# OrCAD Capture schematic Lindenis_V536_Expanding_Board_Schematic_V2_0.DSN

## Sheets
1 13 CON: size A3; title: Lindenis V536; rev: 1.1; note: CON
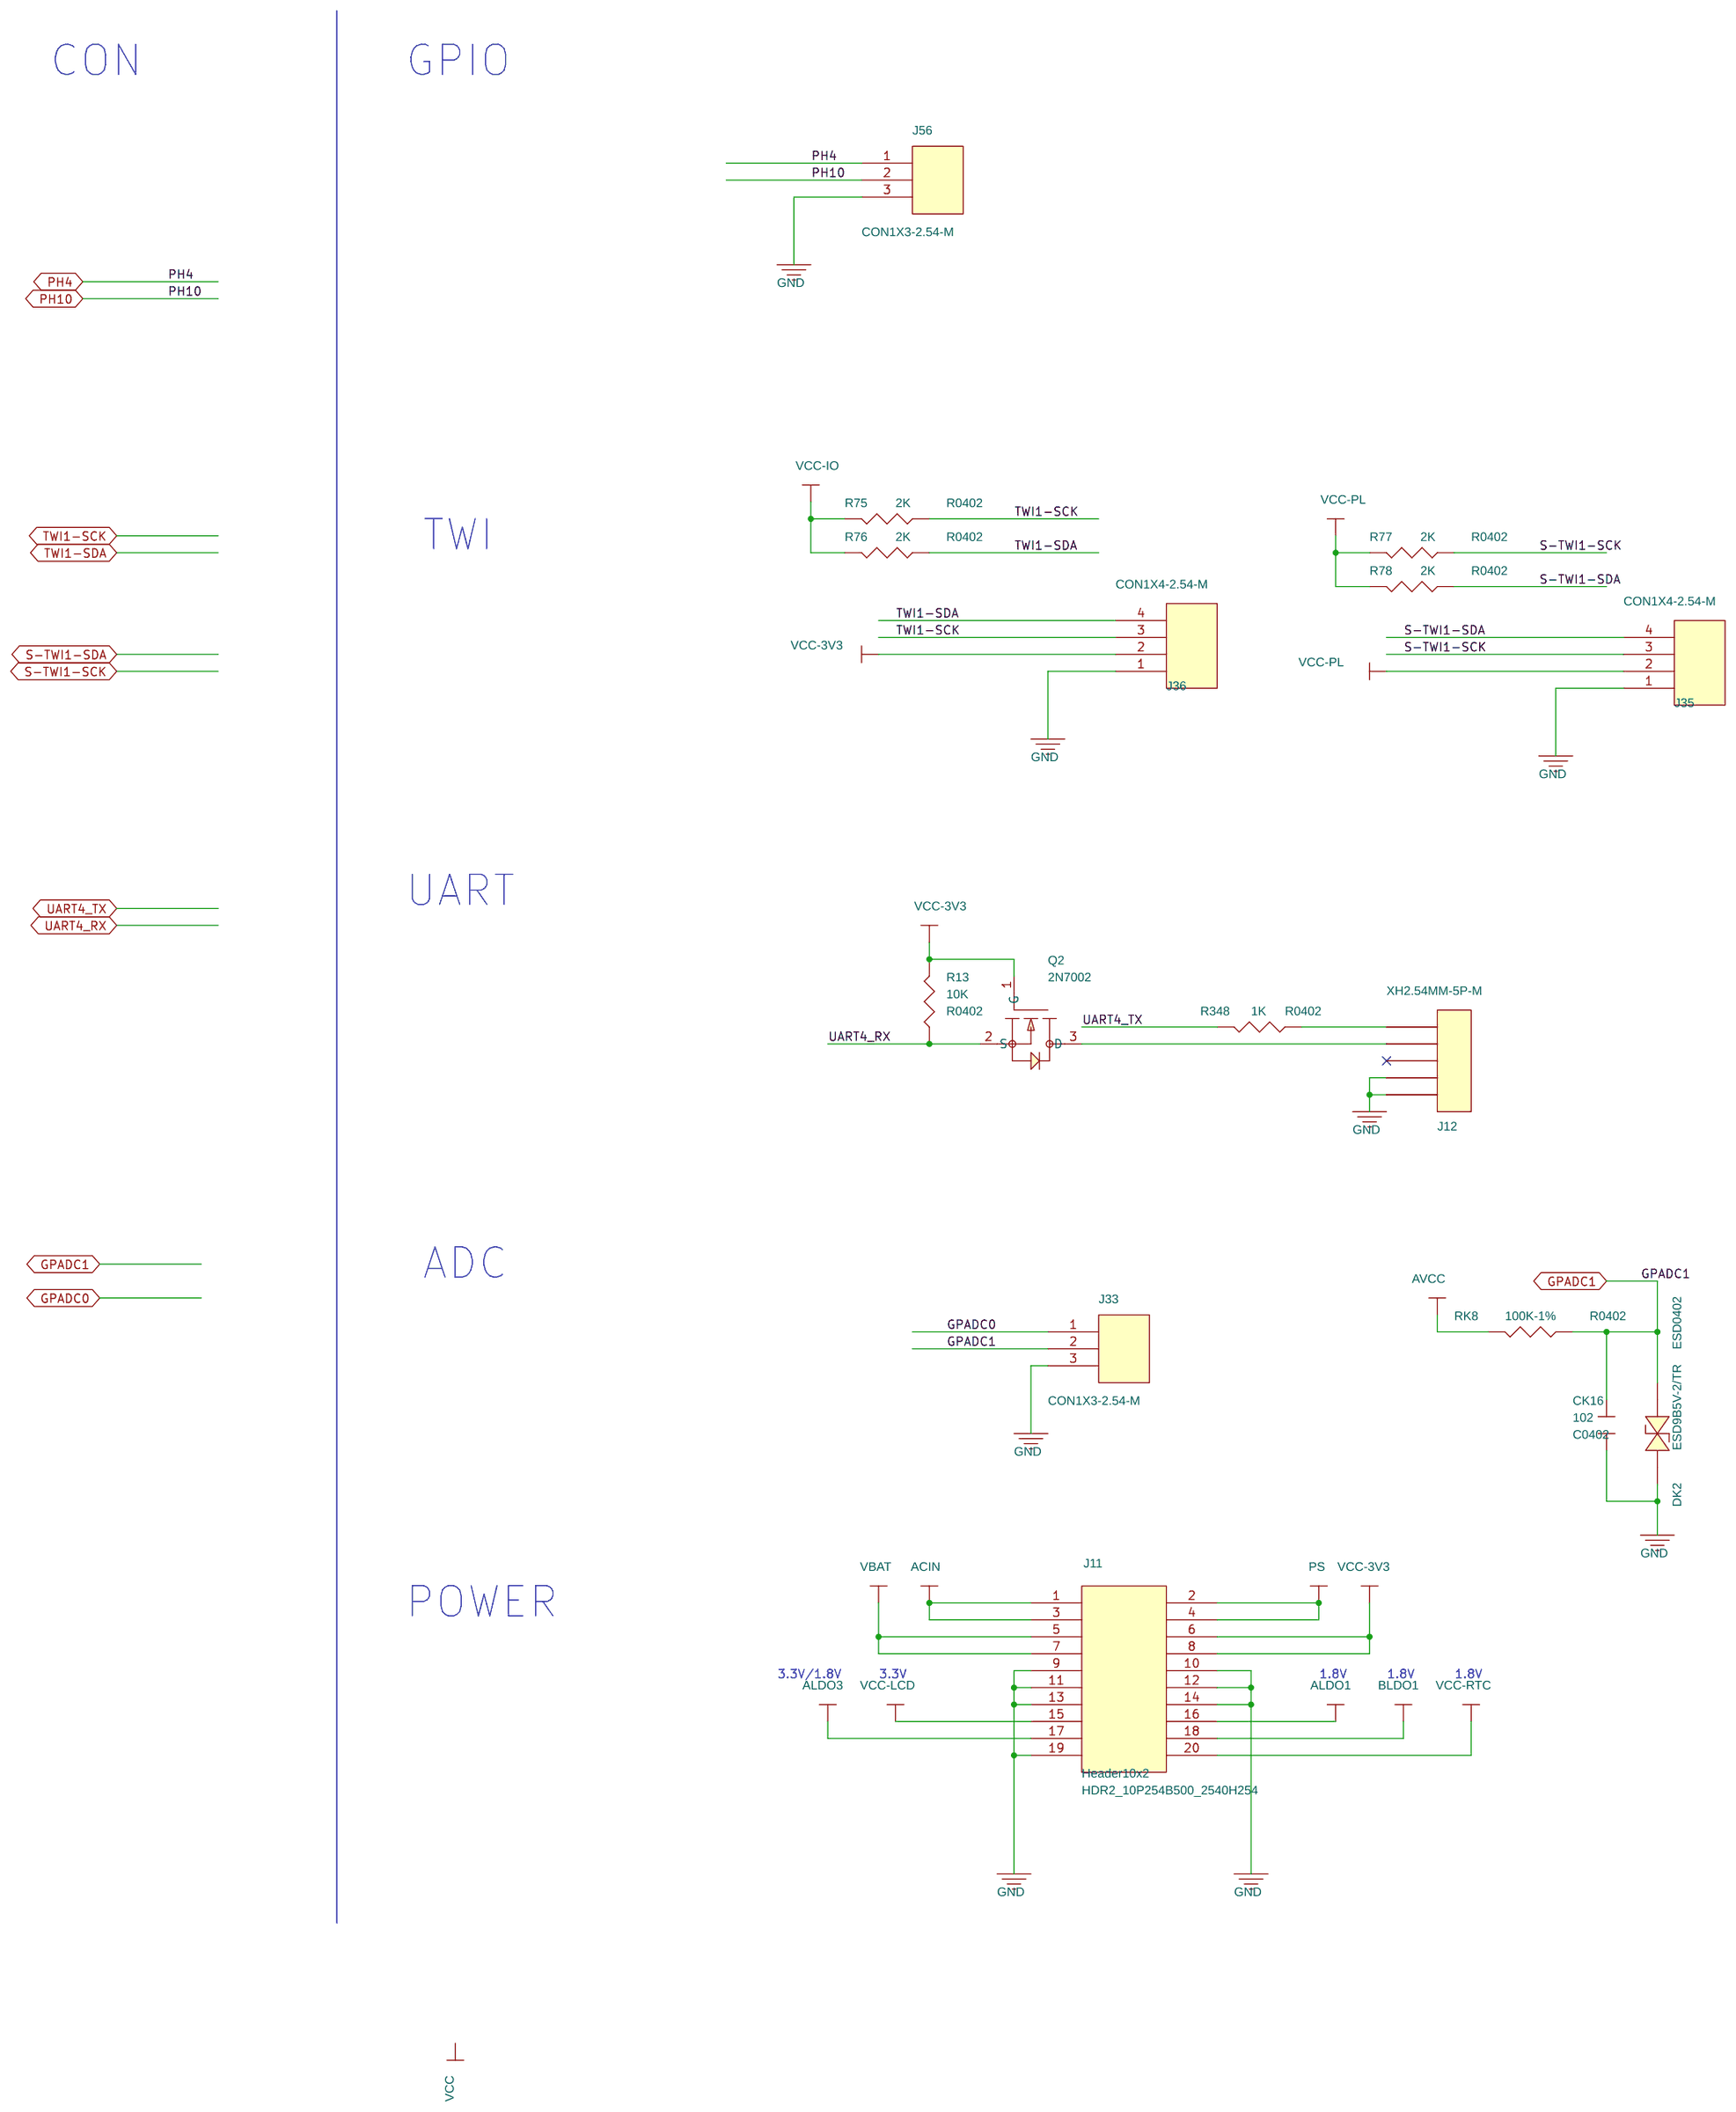
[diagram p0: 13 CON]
2 06 HDMI: size A3; note: HDMI
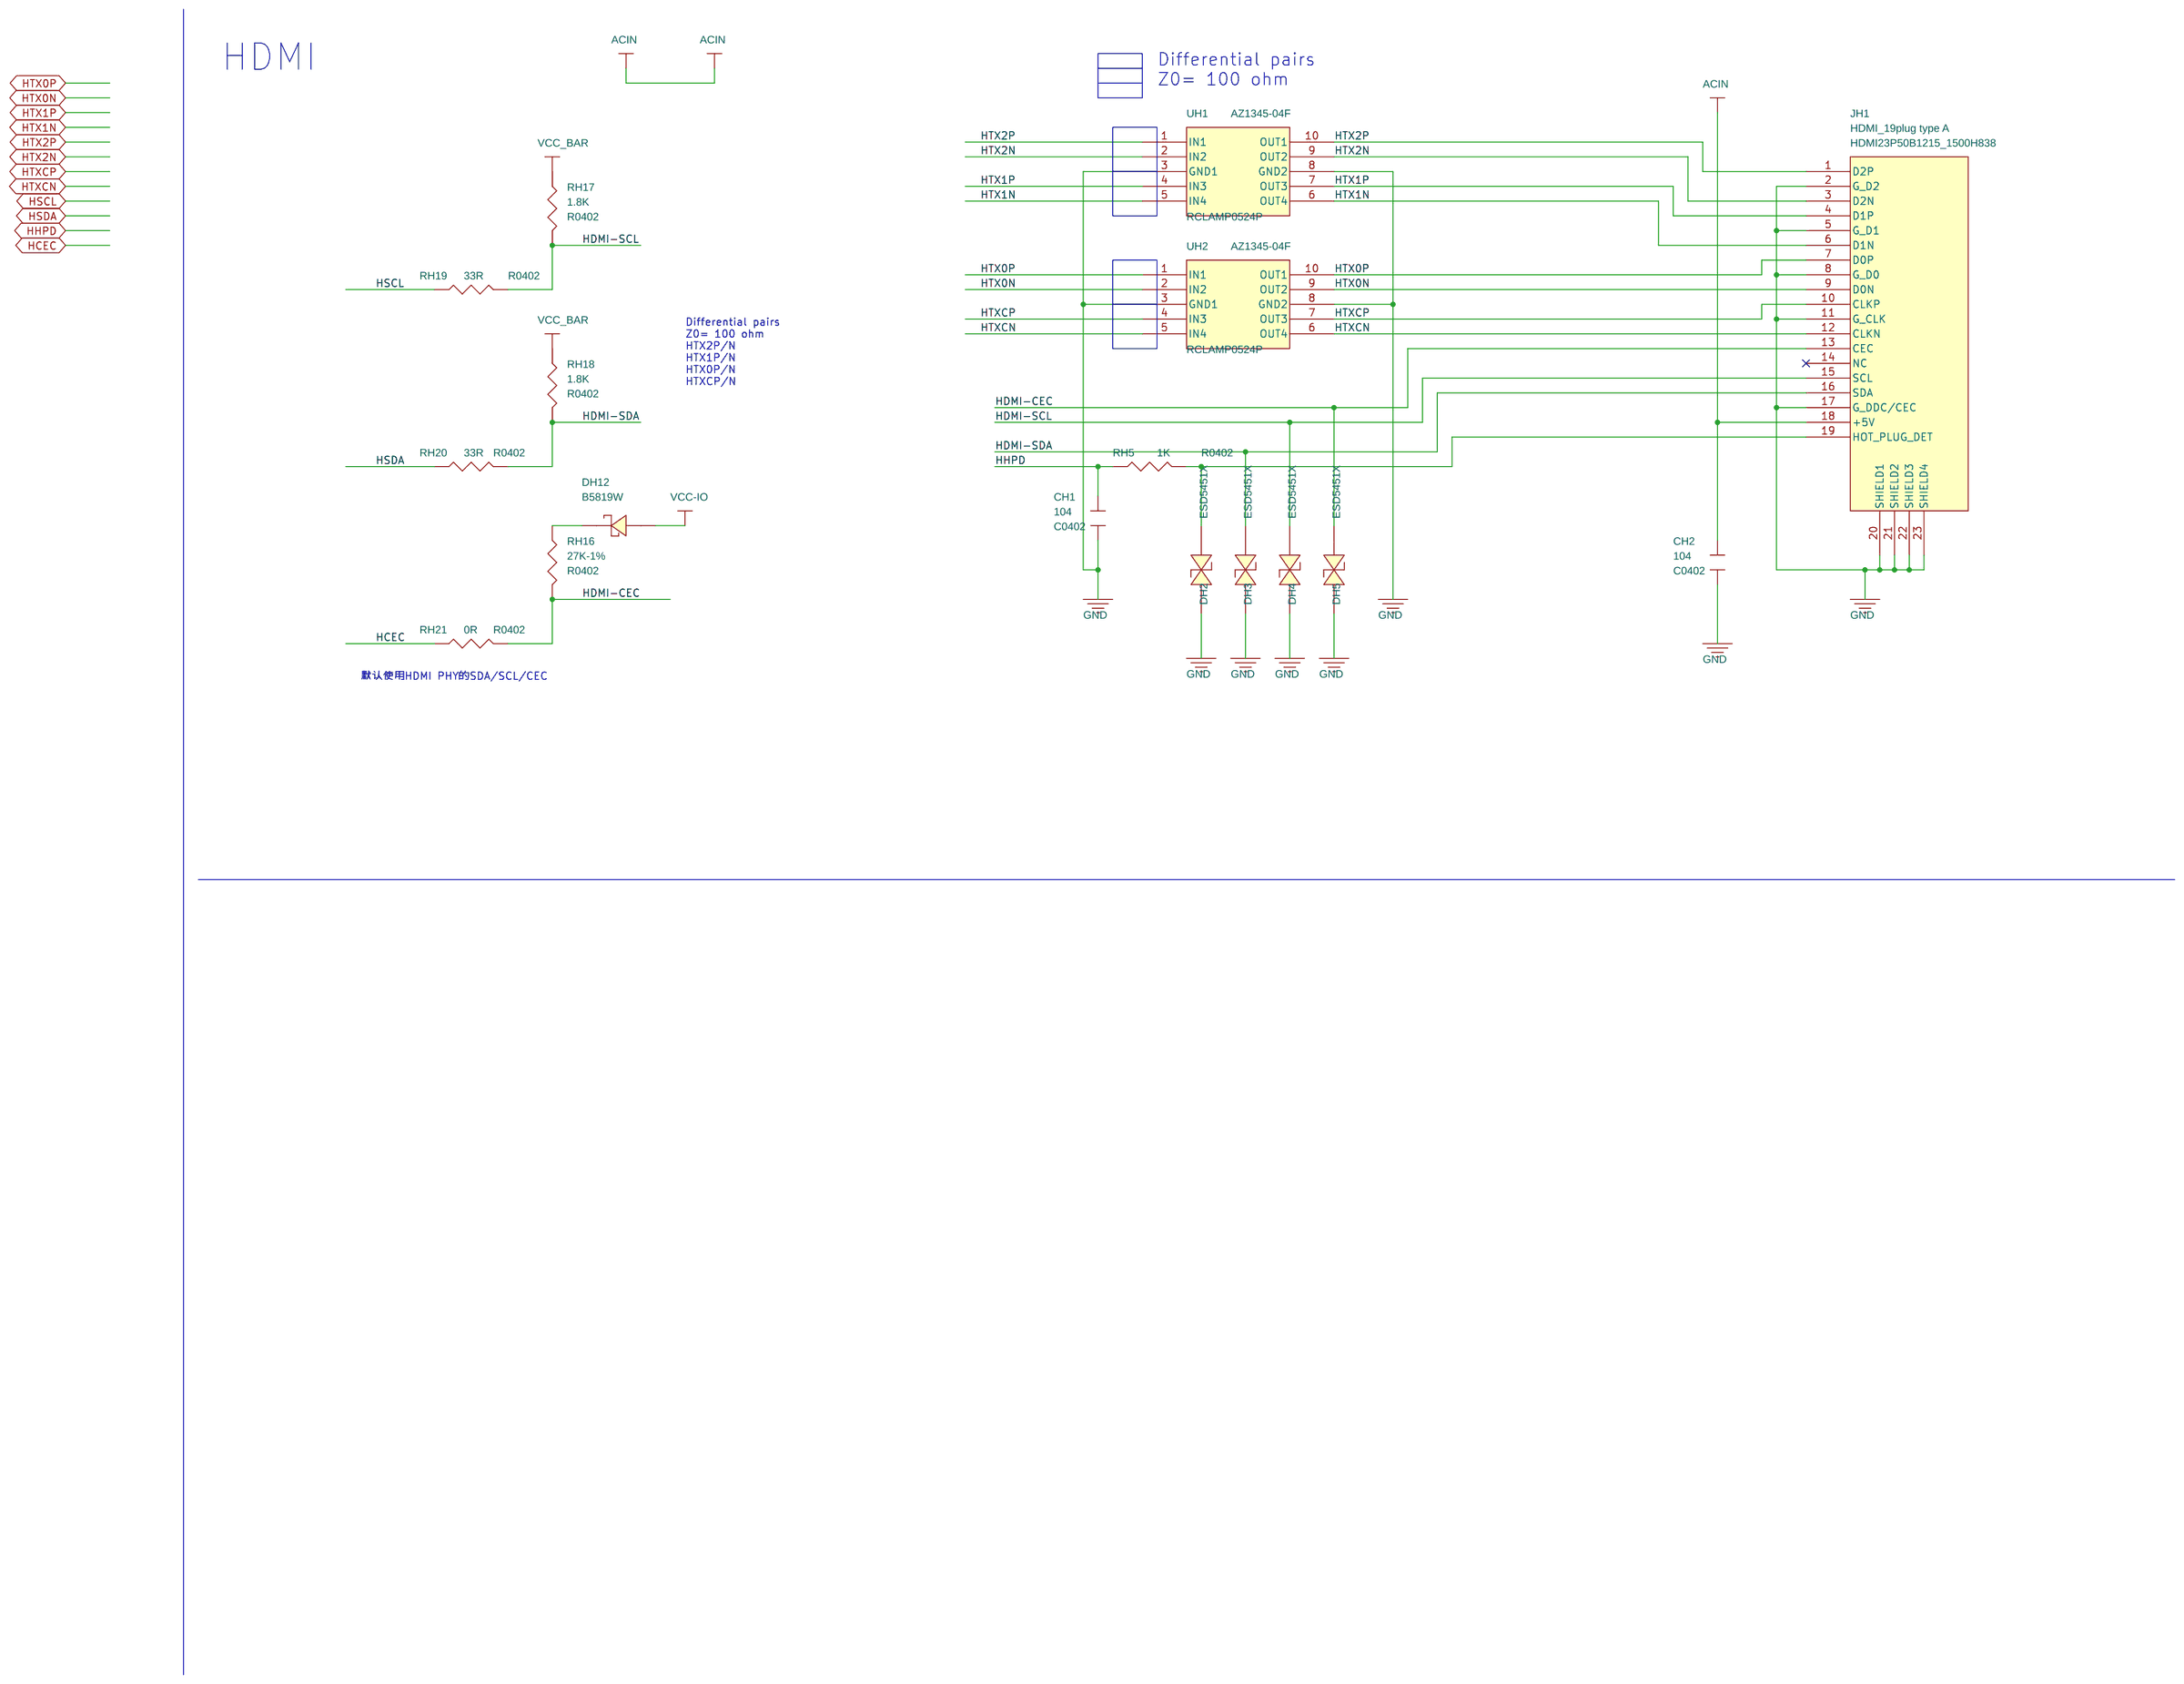
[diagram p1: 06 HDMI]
3 12 GMAC: size A3; note: ETHERNET
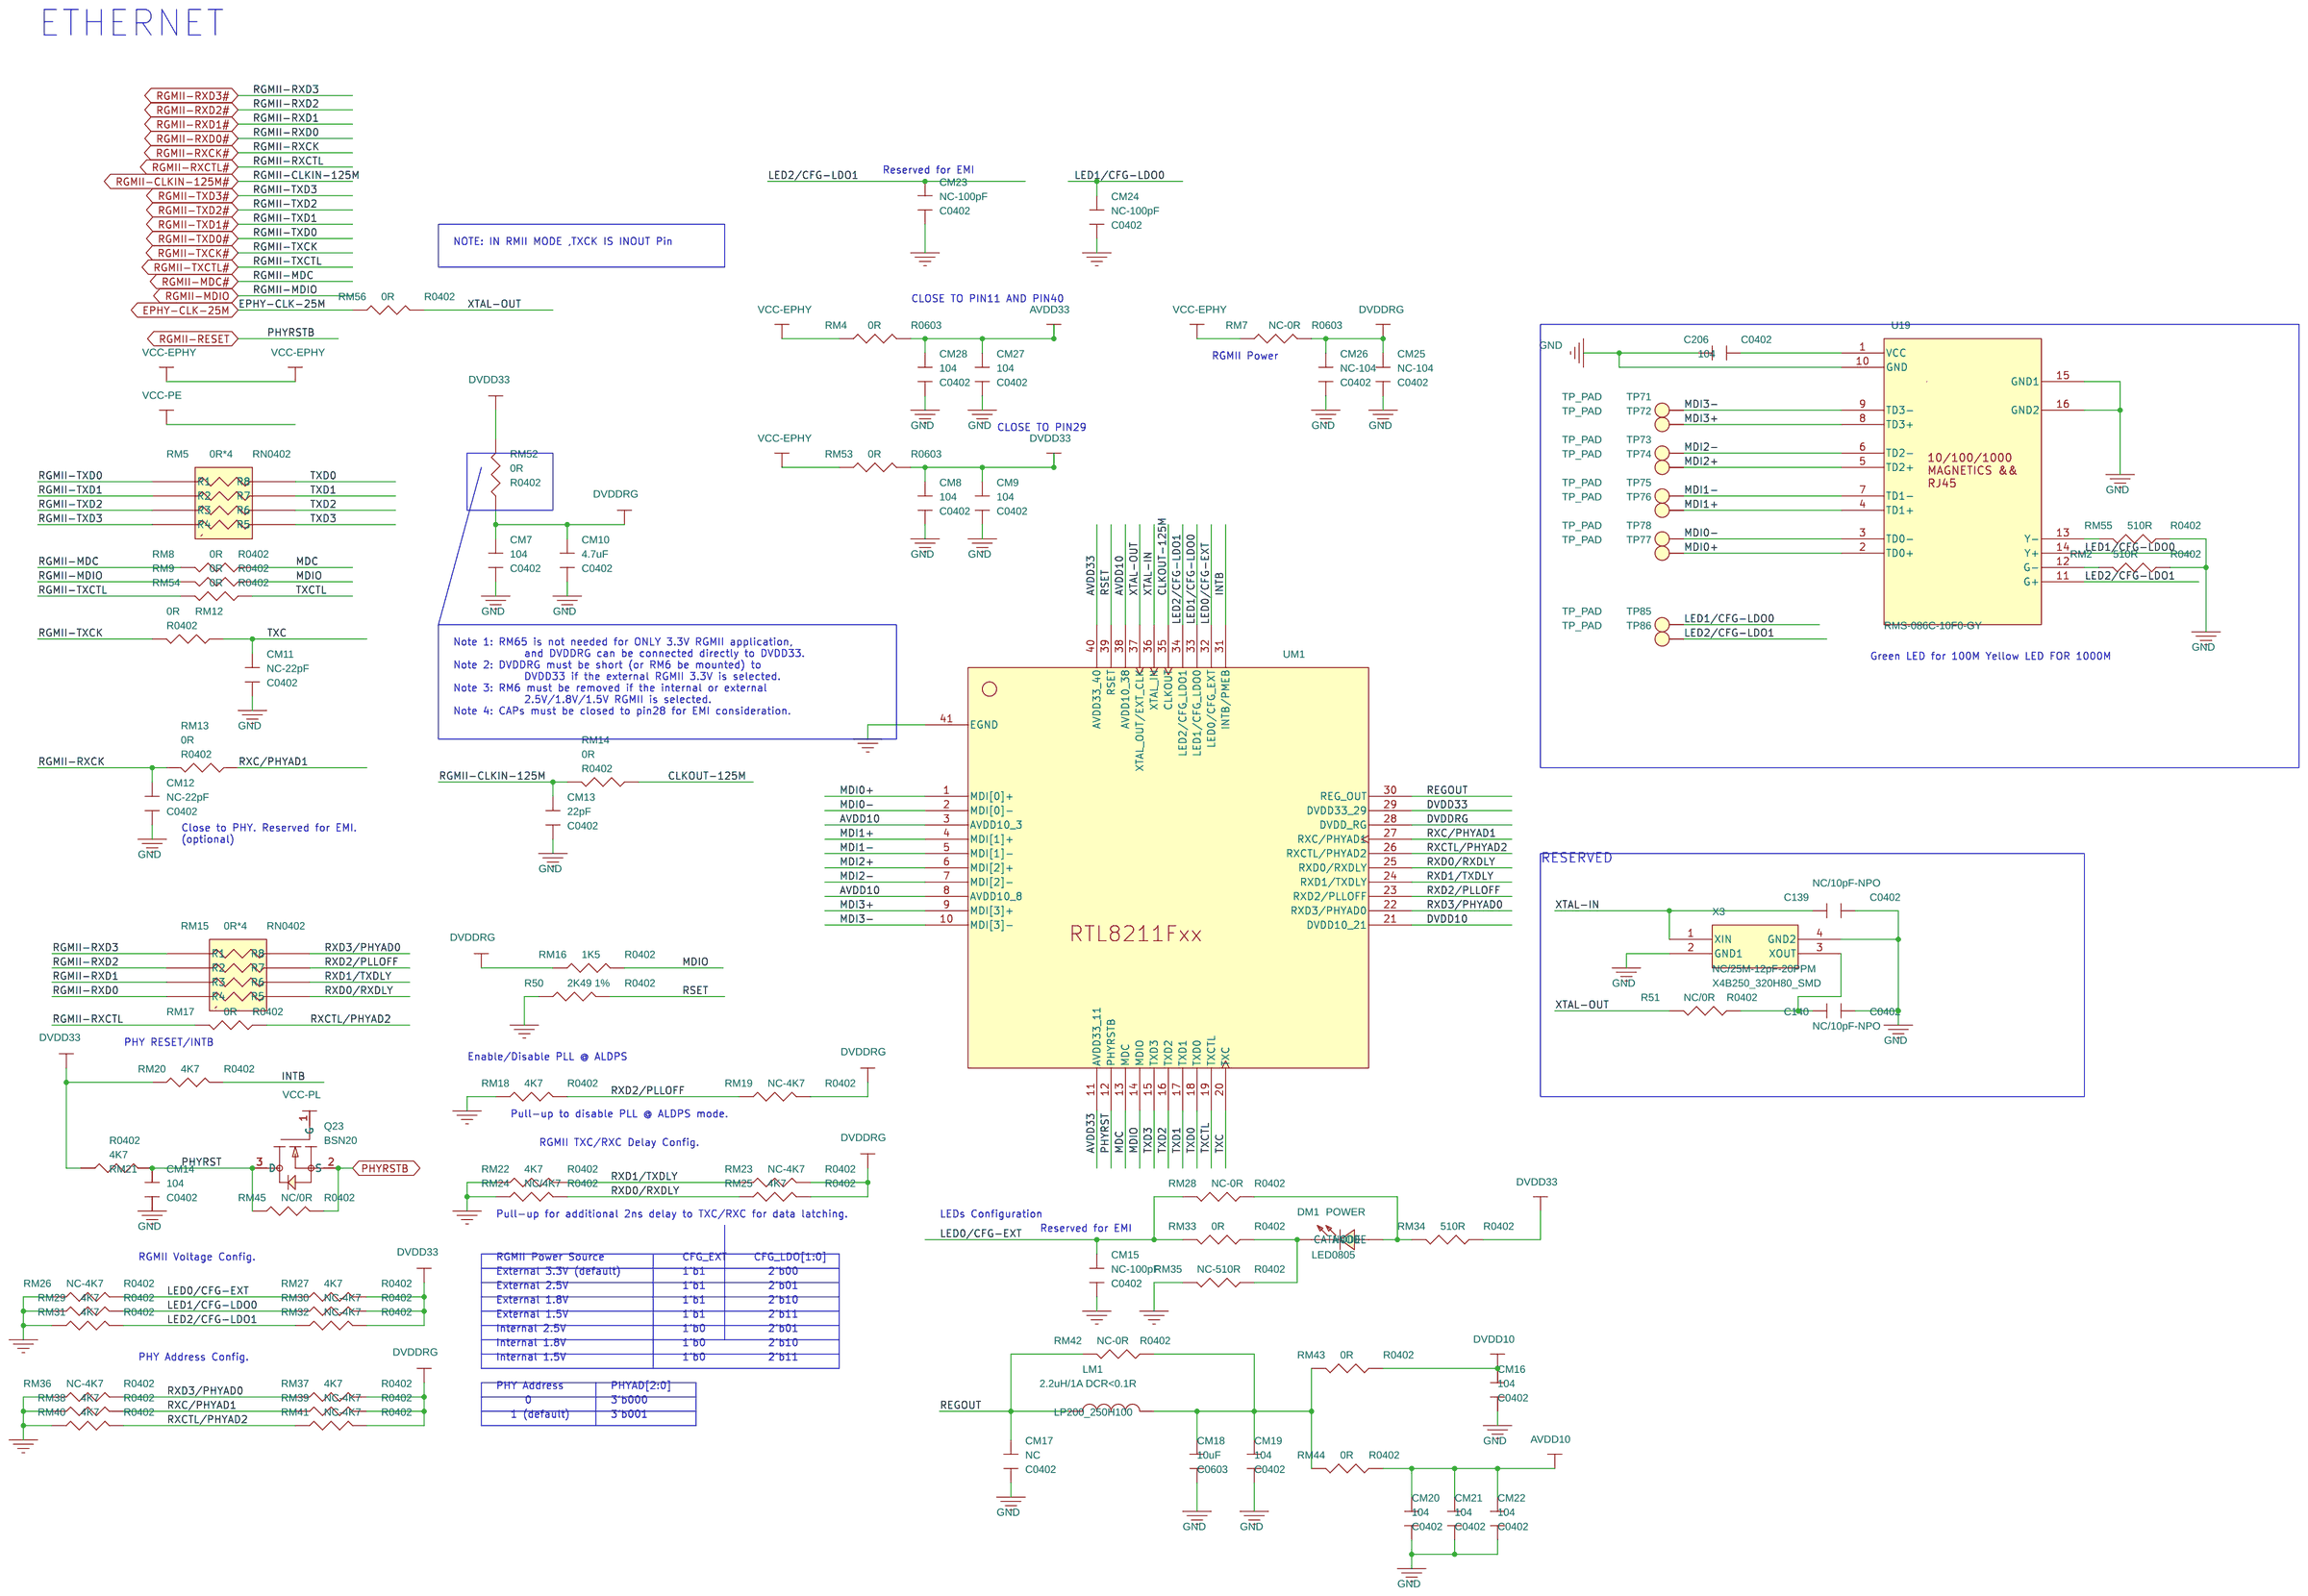
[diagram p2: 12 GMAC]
4 11 4G-SIM7600CE: size A3; title: Lindenis Airdoc V5; note: SIM7600CE
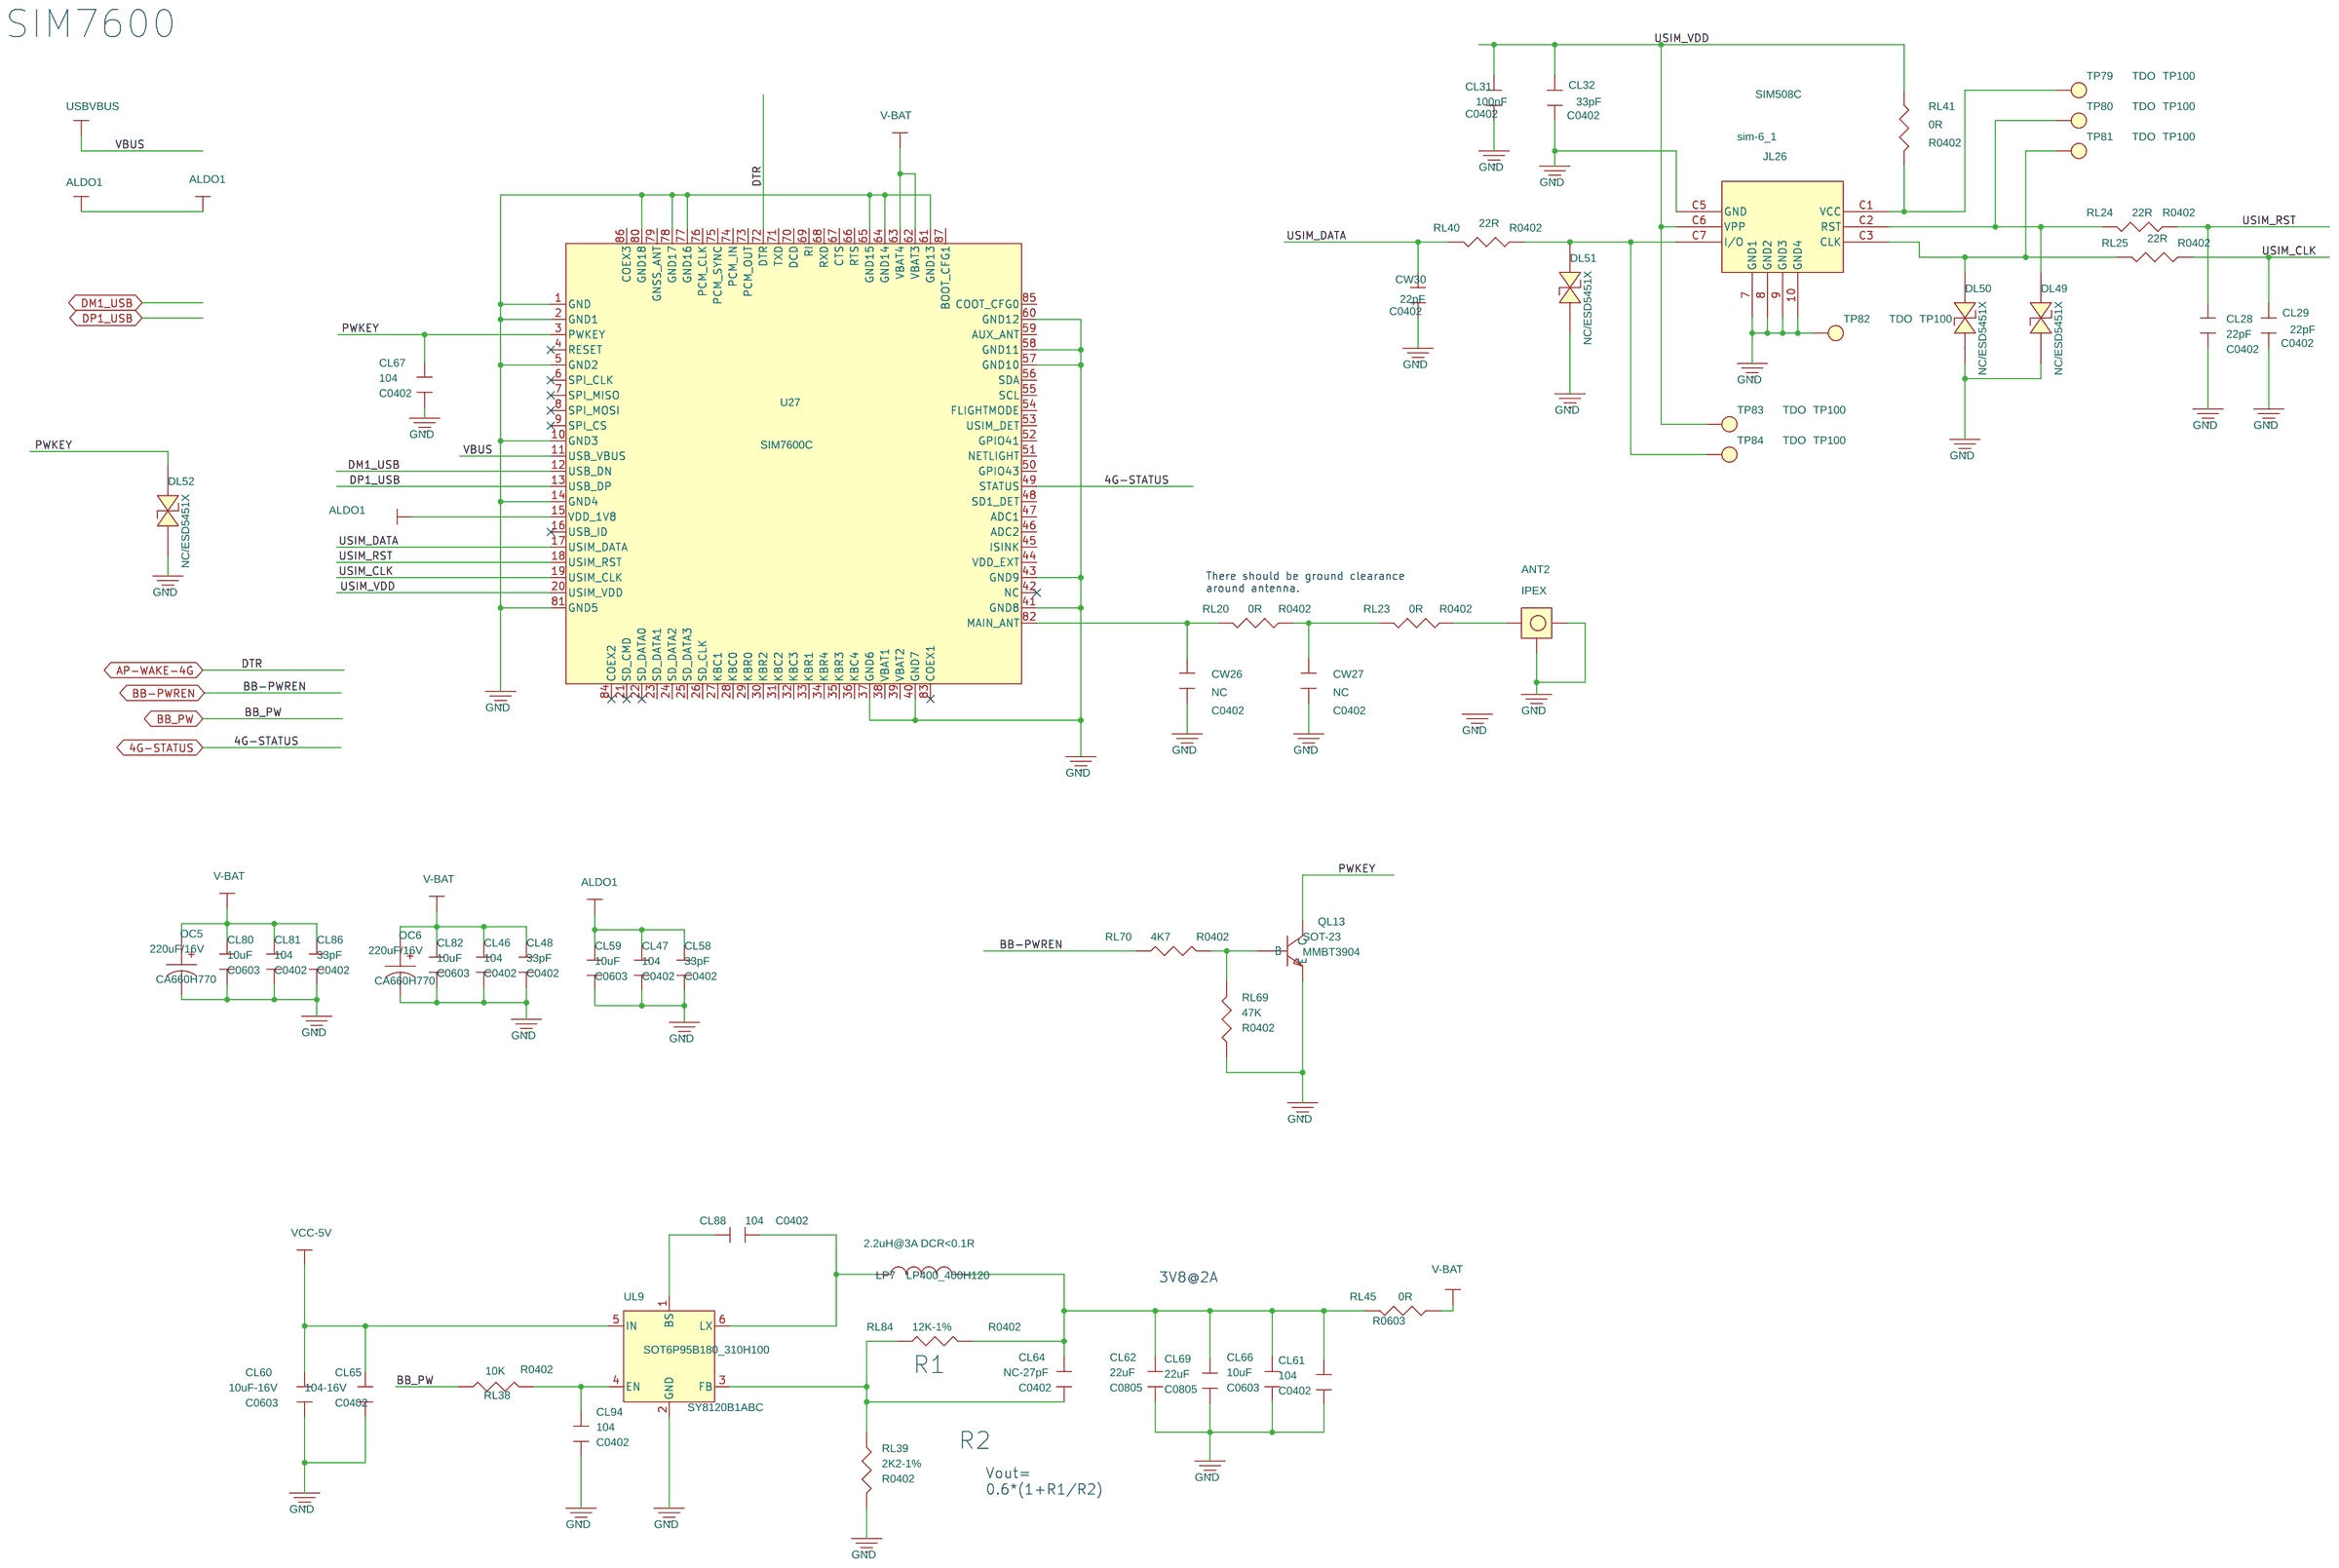
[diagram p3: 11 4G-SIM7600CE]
5 02 V536MODE: size A3; note: MODE
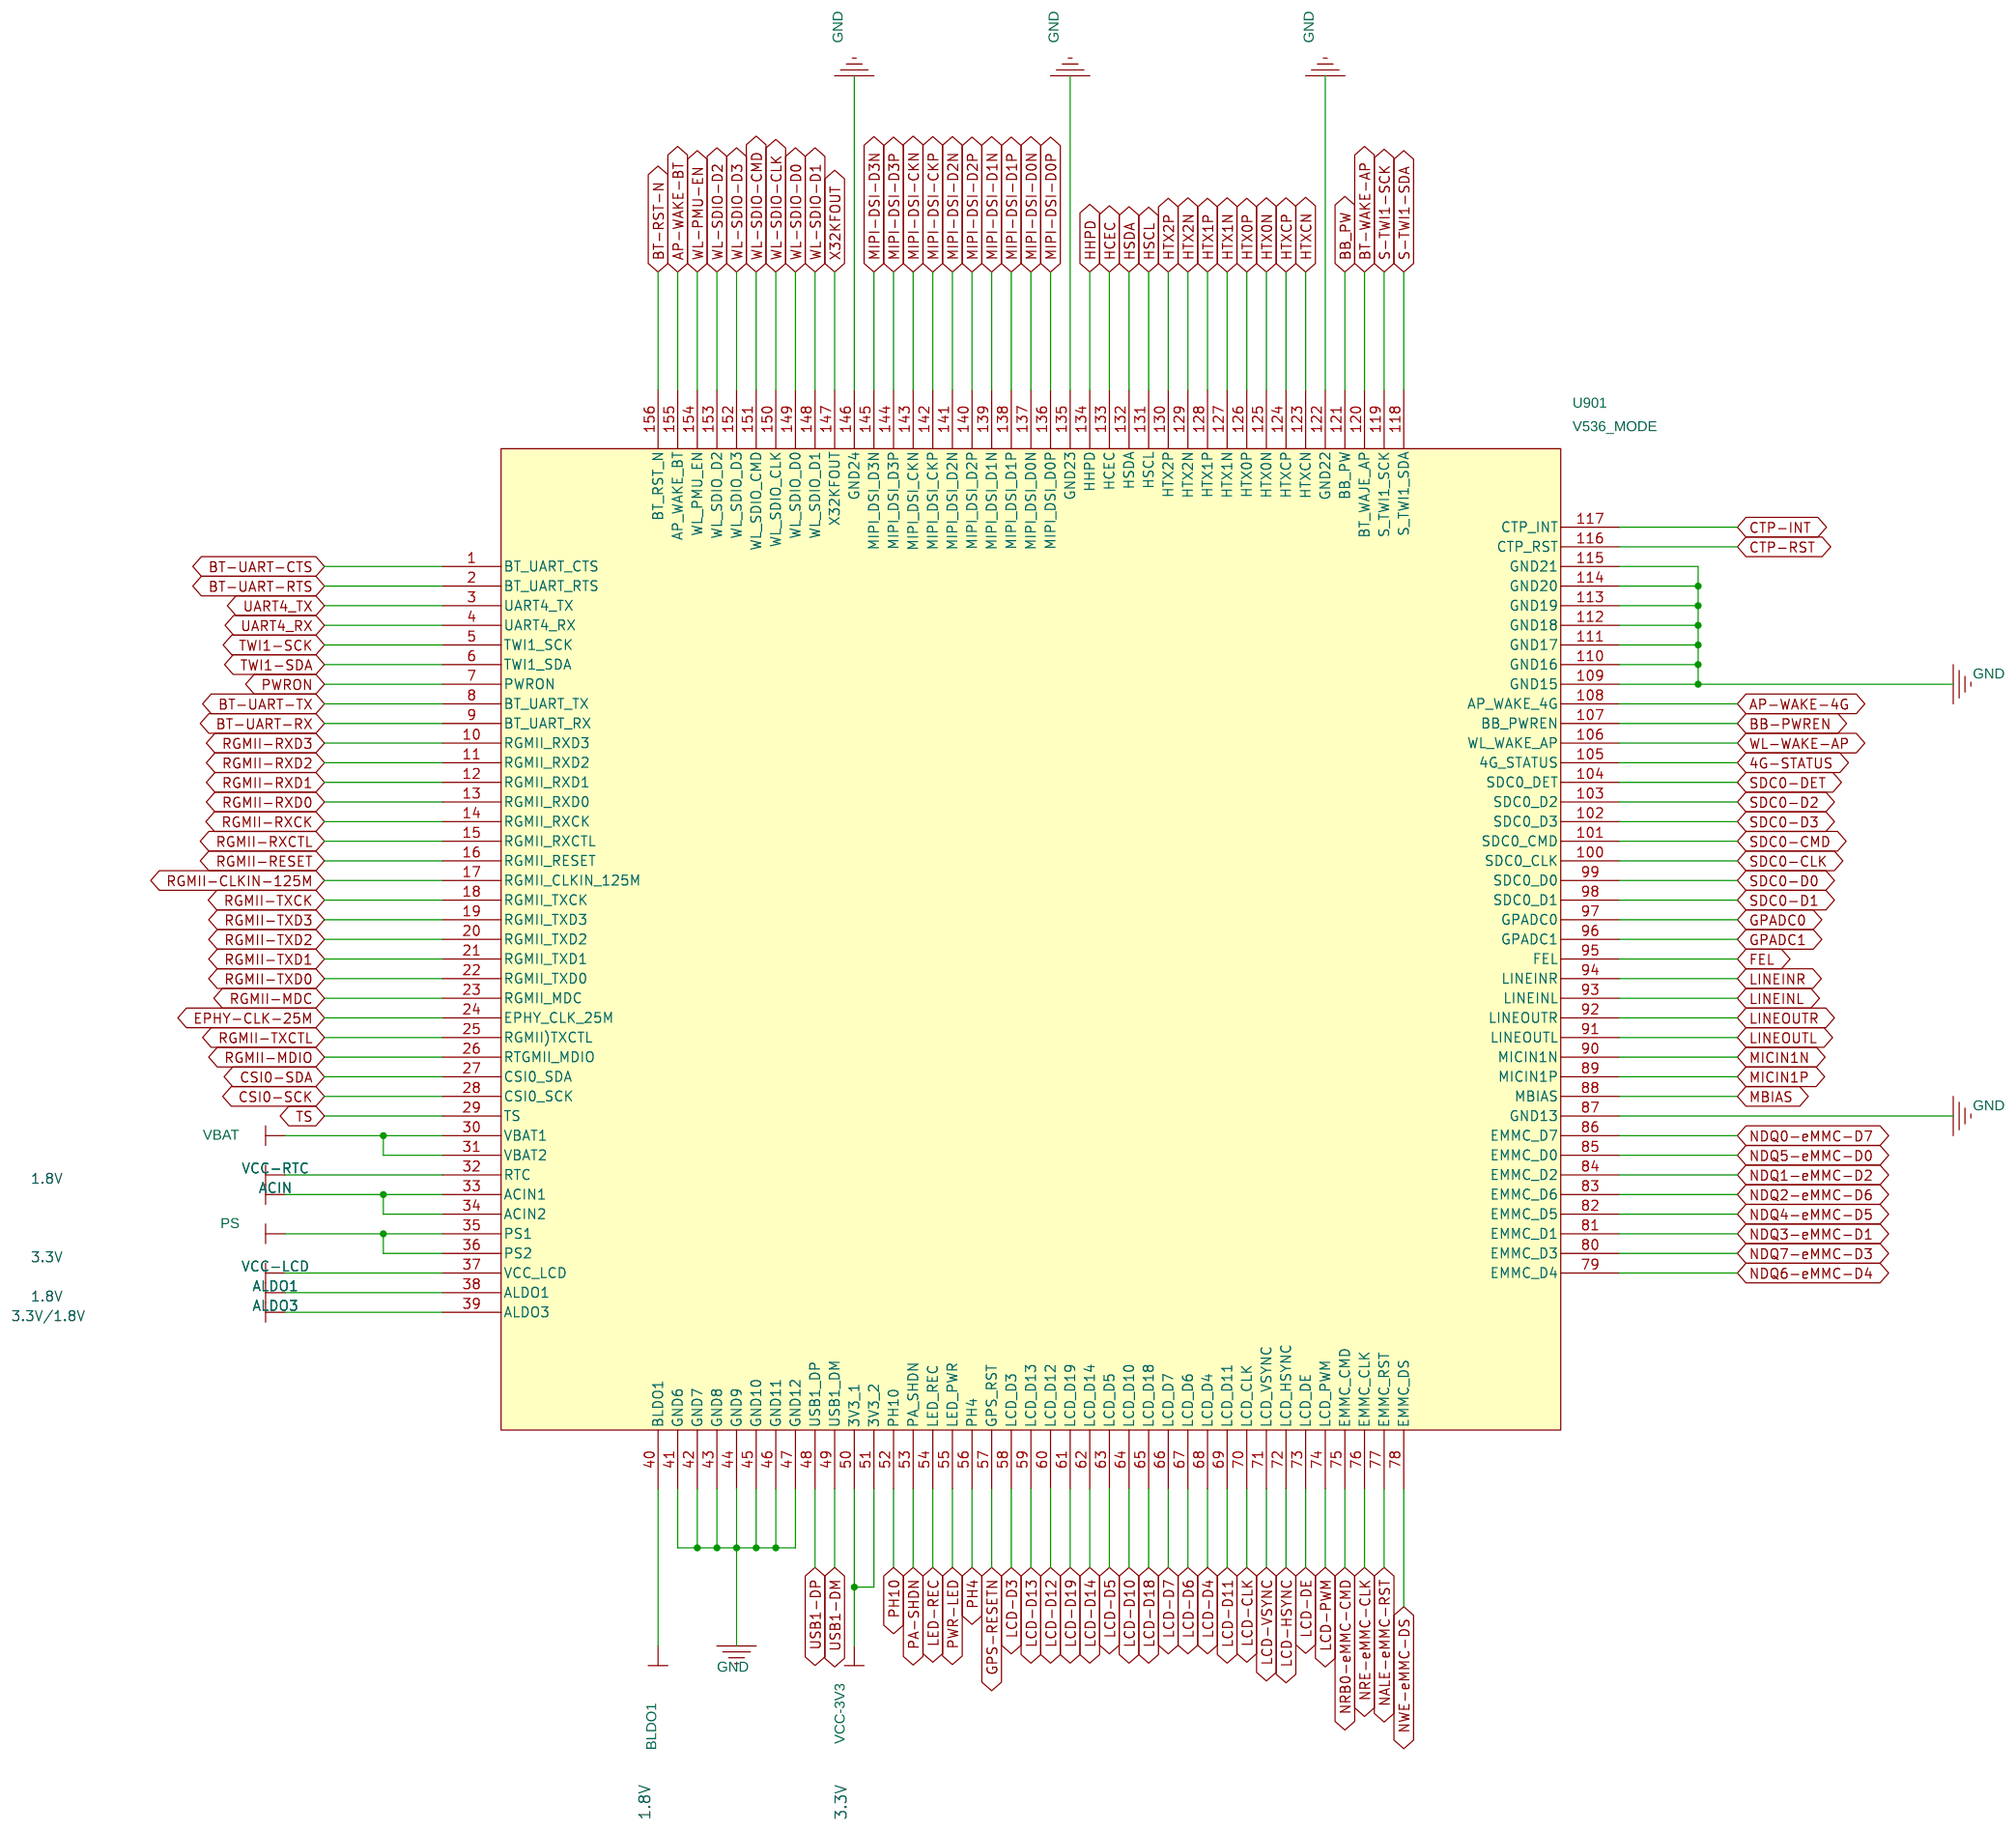
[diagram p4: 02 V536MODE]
6 10 WIFI: size A3; note: WIFI
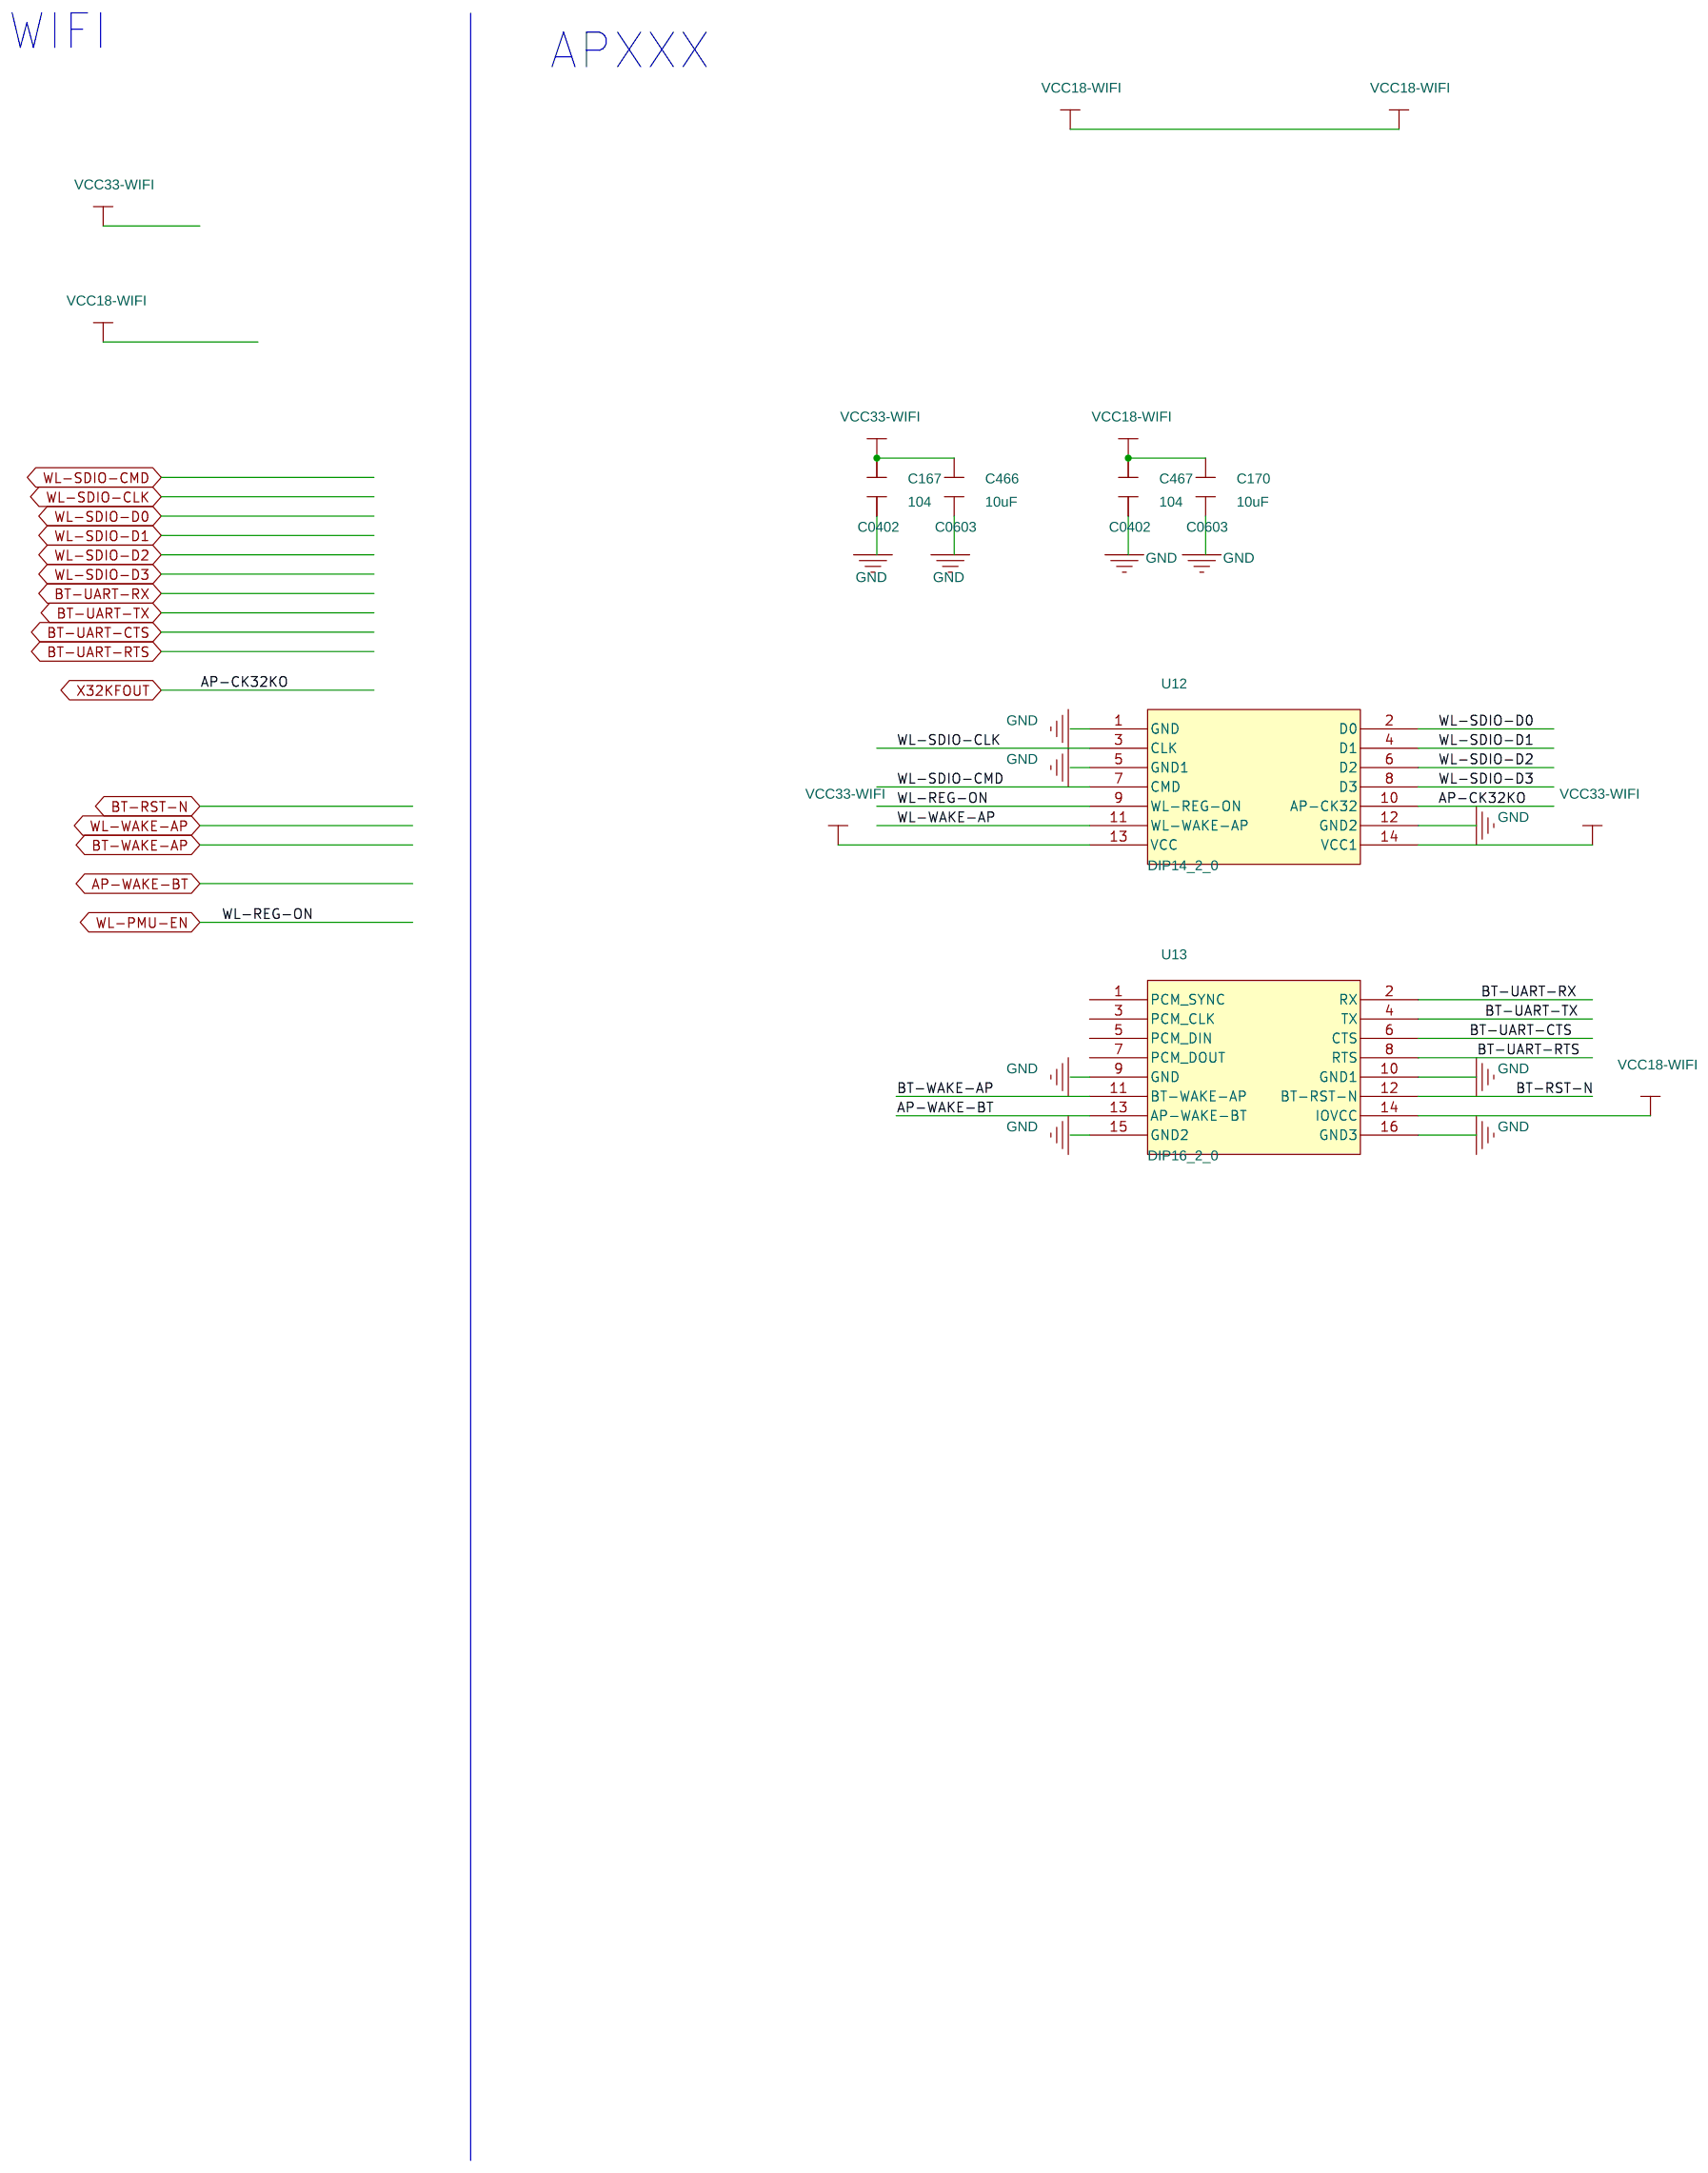
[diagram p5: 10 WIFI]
7 05 AUDIO: size A2; note: AUDIO
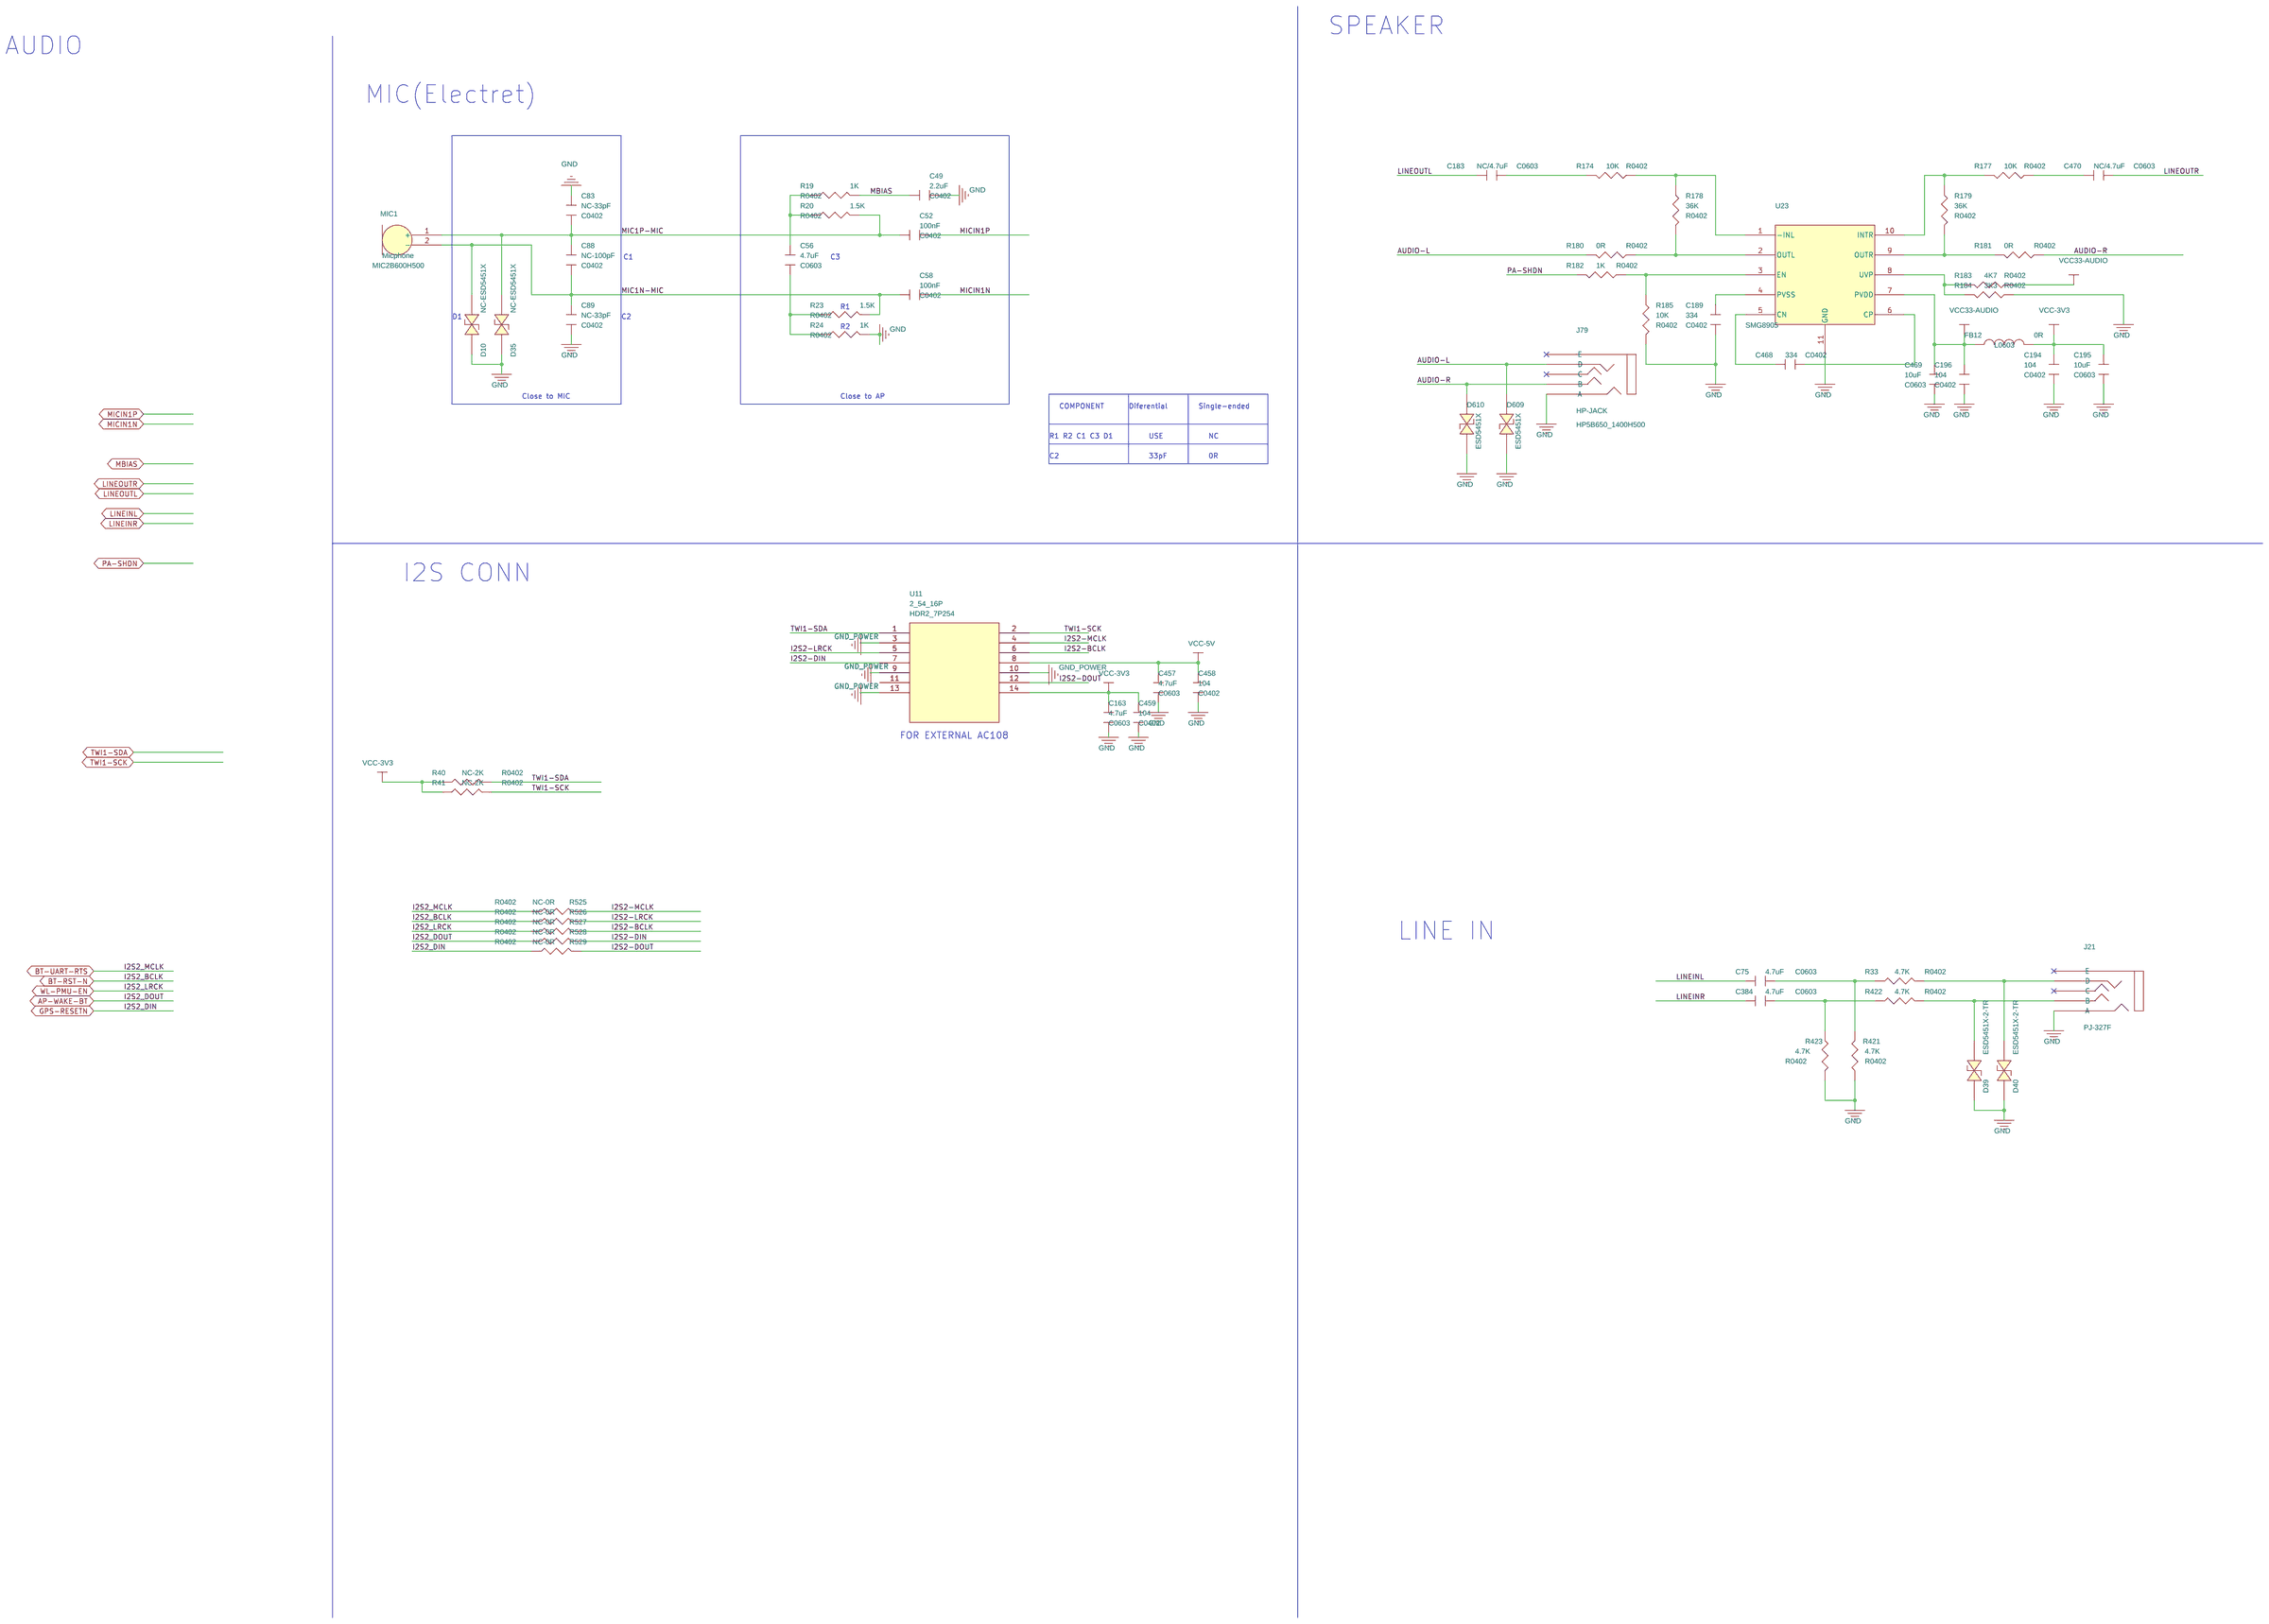
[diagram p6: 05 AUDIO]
8 01 POWER-AXP2101: size A3; note: POWER
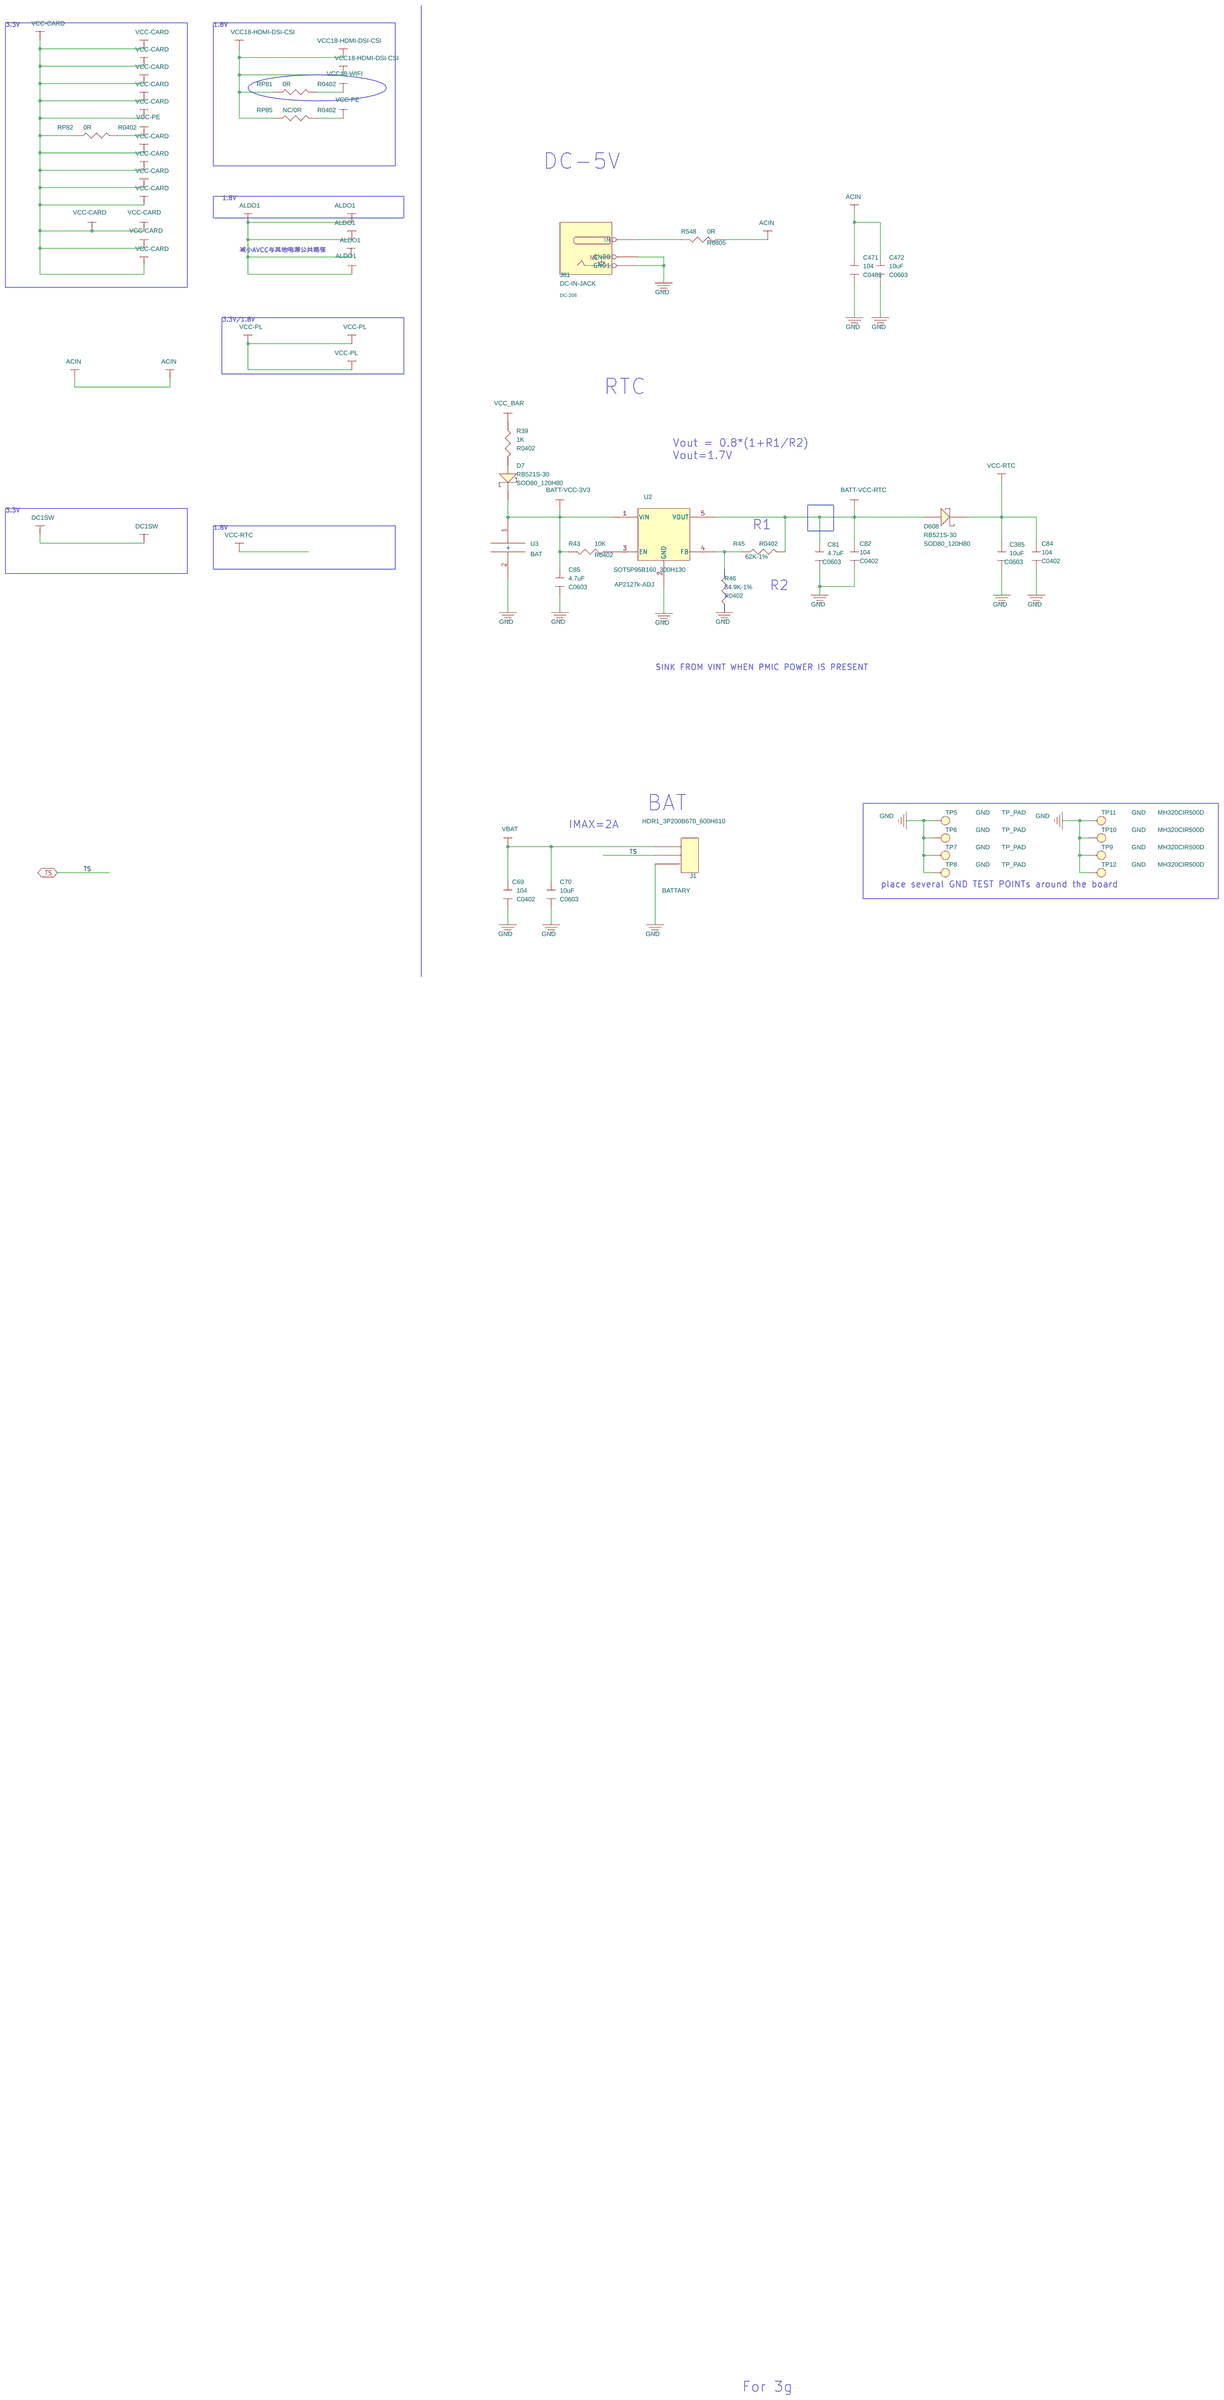
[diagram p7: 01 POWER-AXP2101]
9 03 EMMC: size A3; note: EMMC
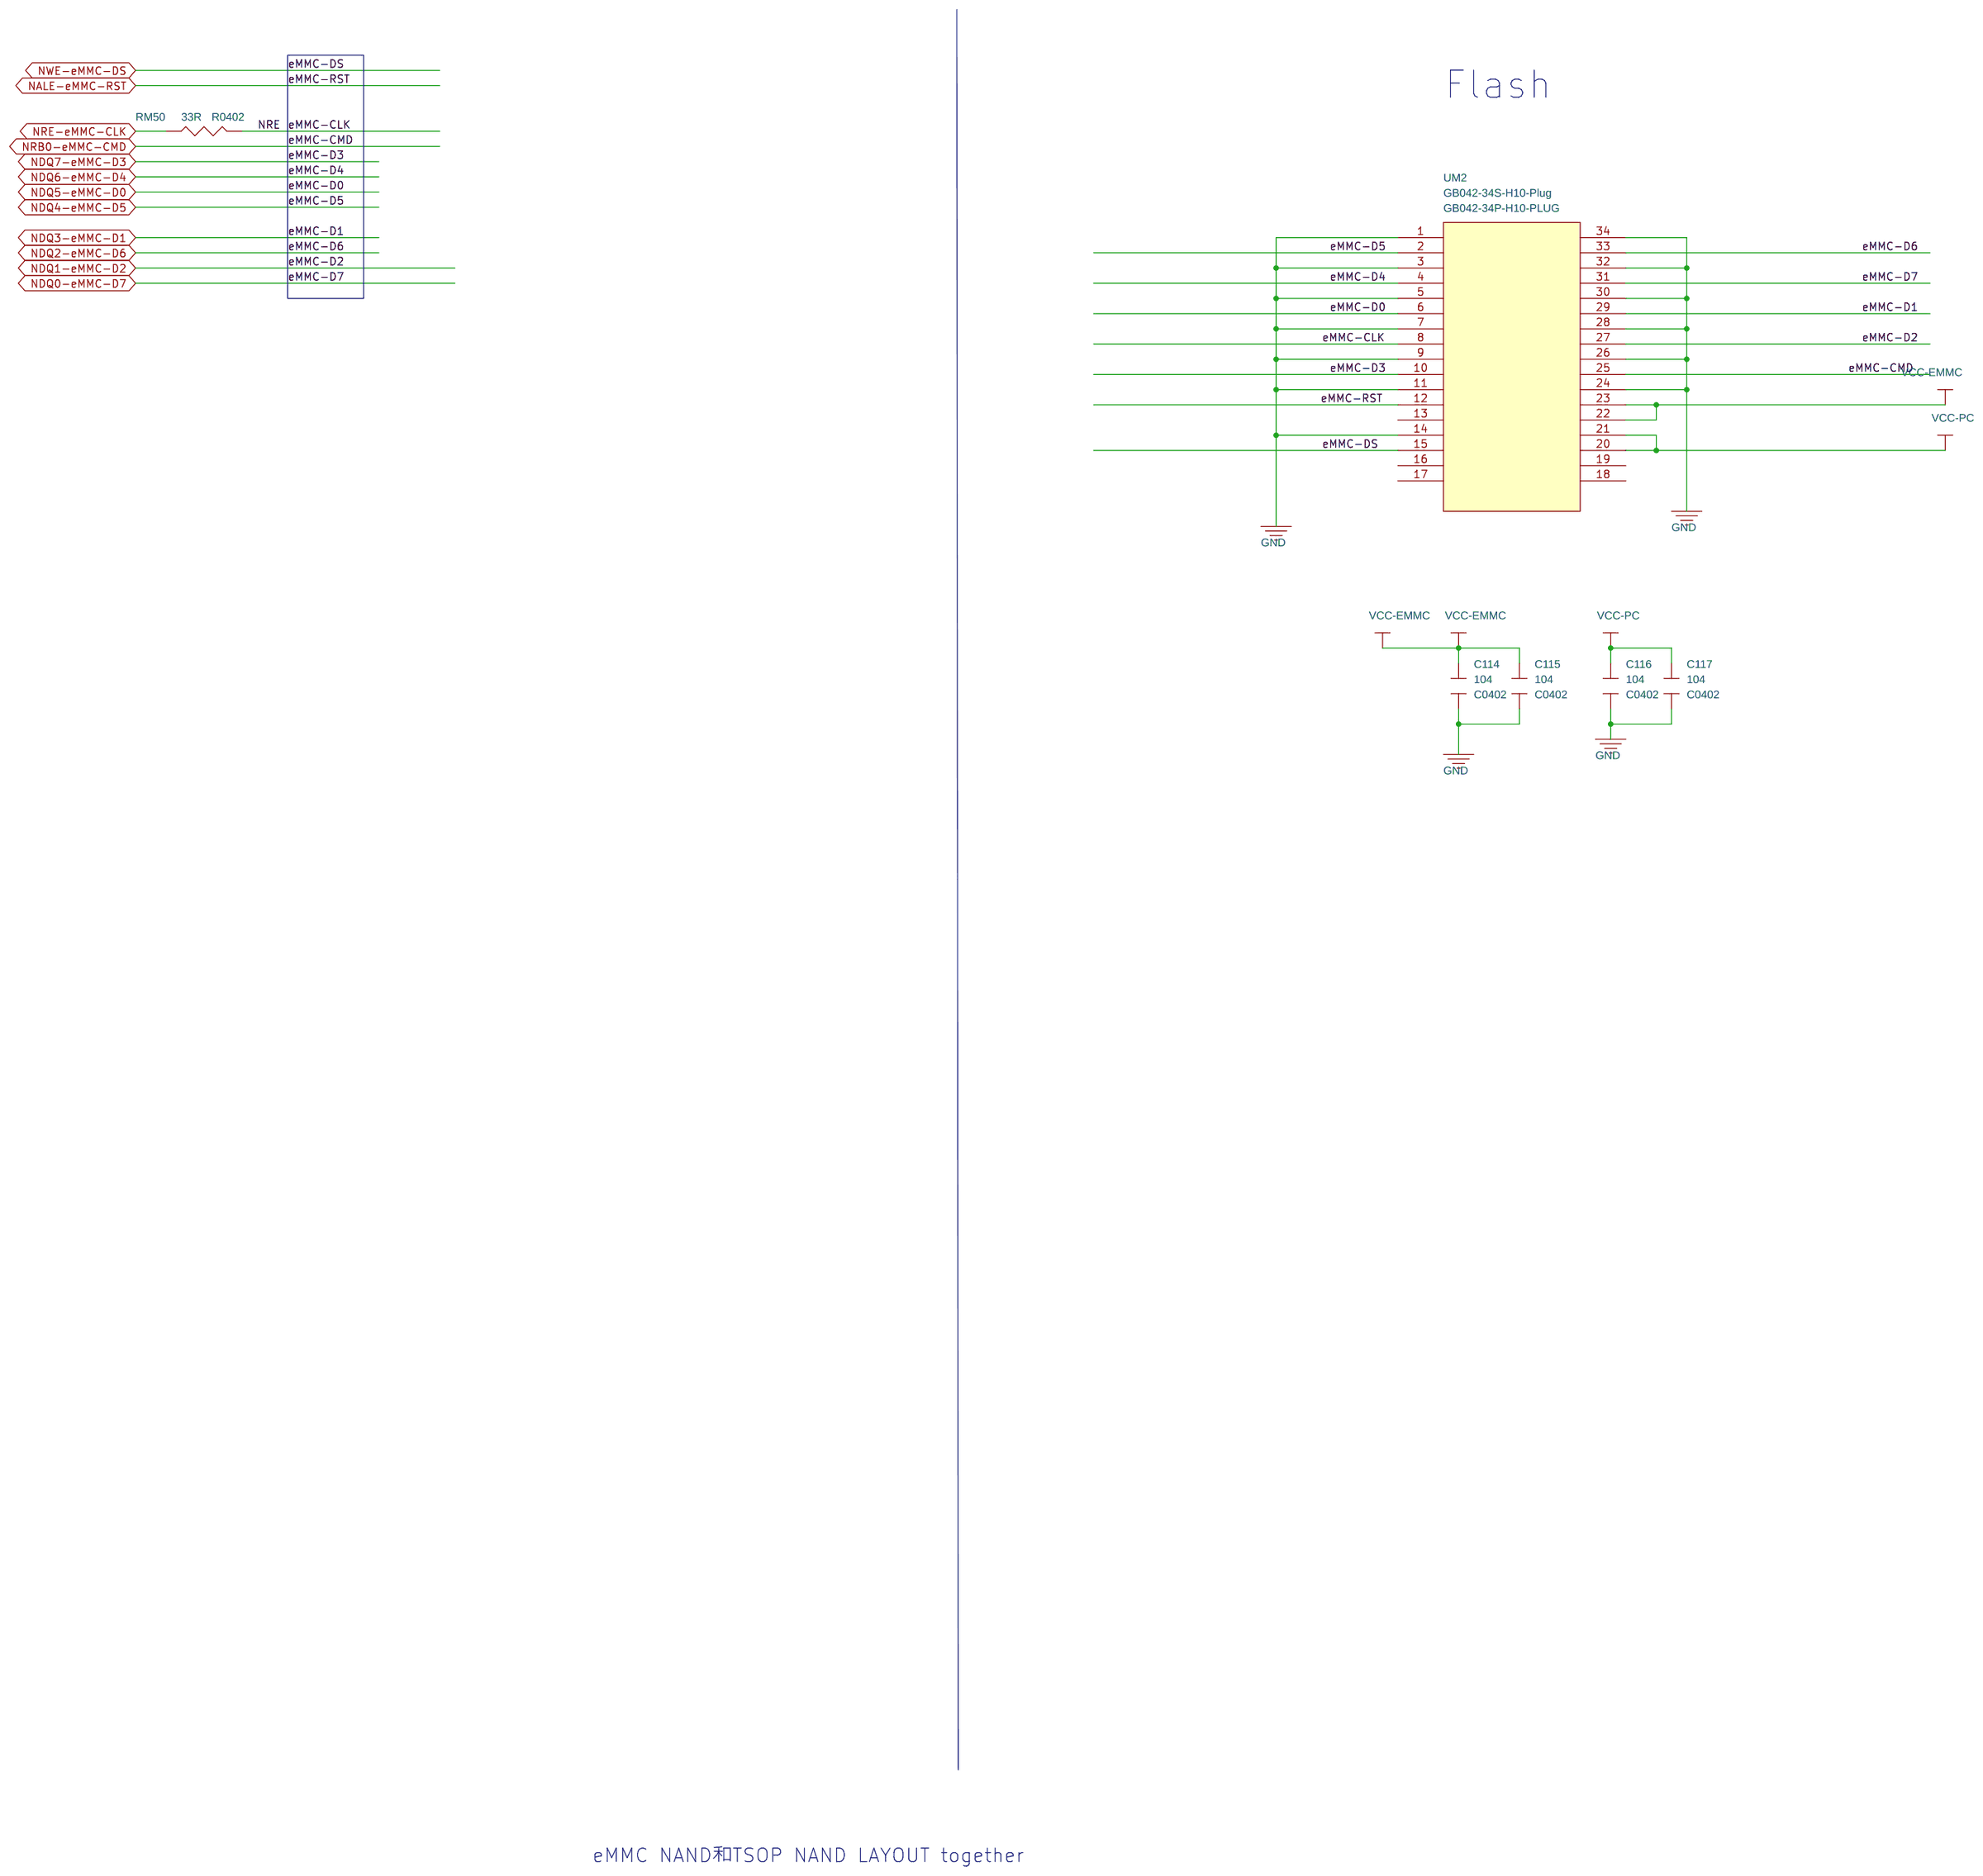
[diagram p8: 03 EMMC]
10 07 KEY/DVP-CSI: size A3; note: KEY/CSI
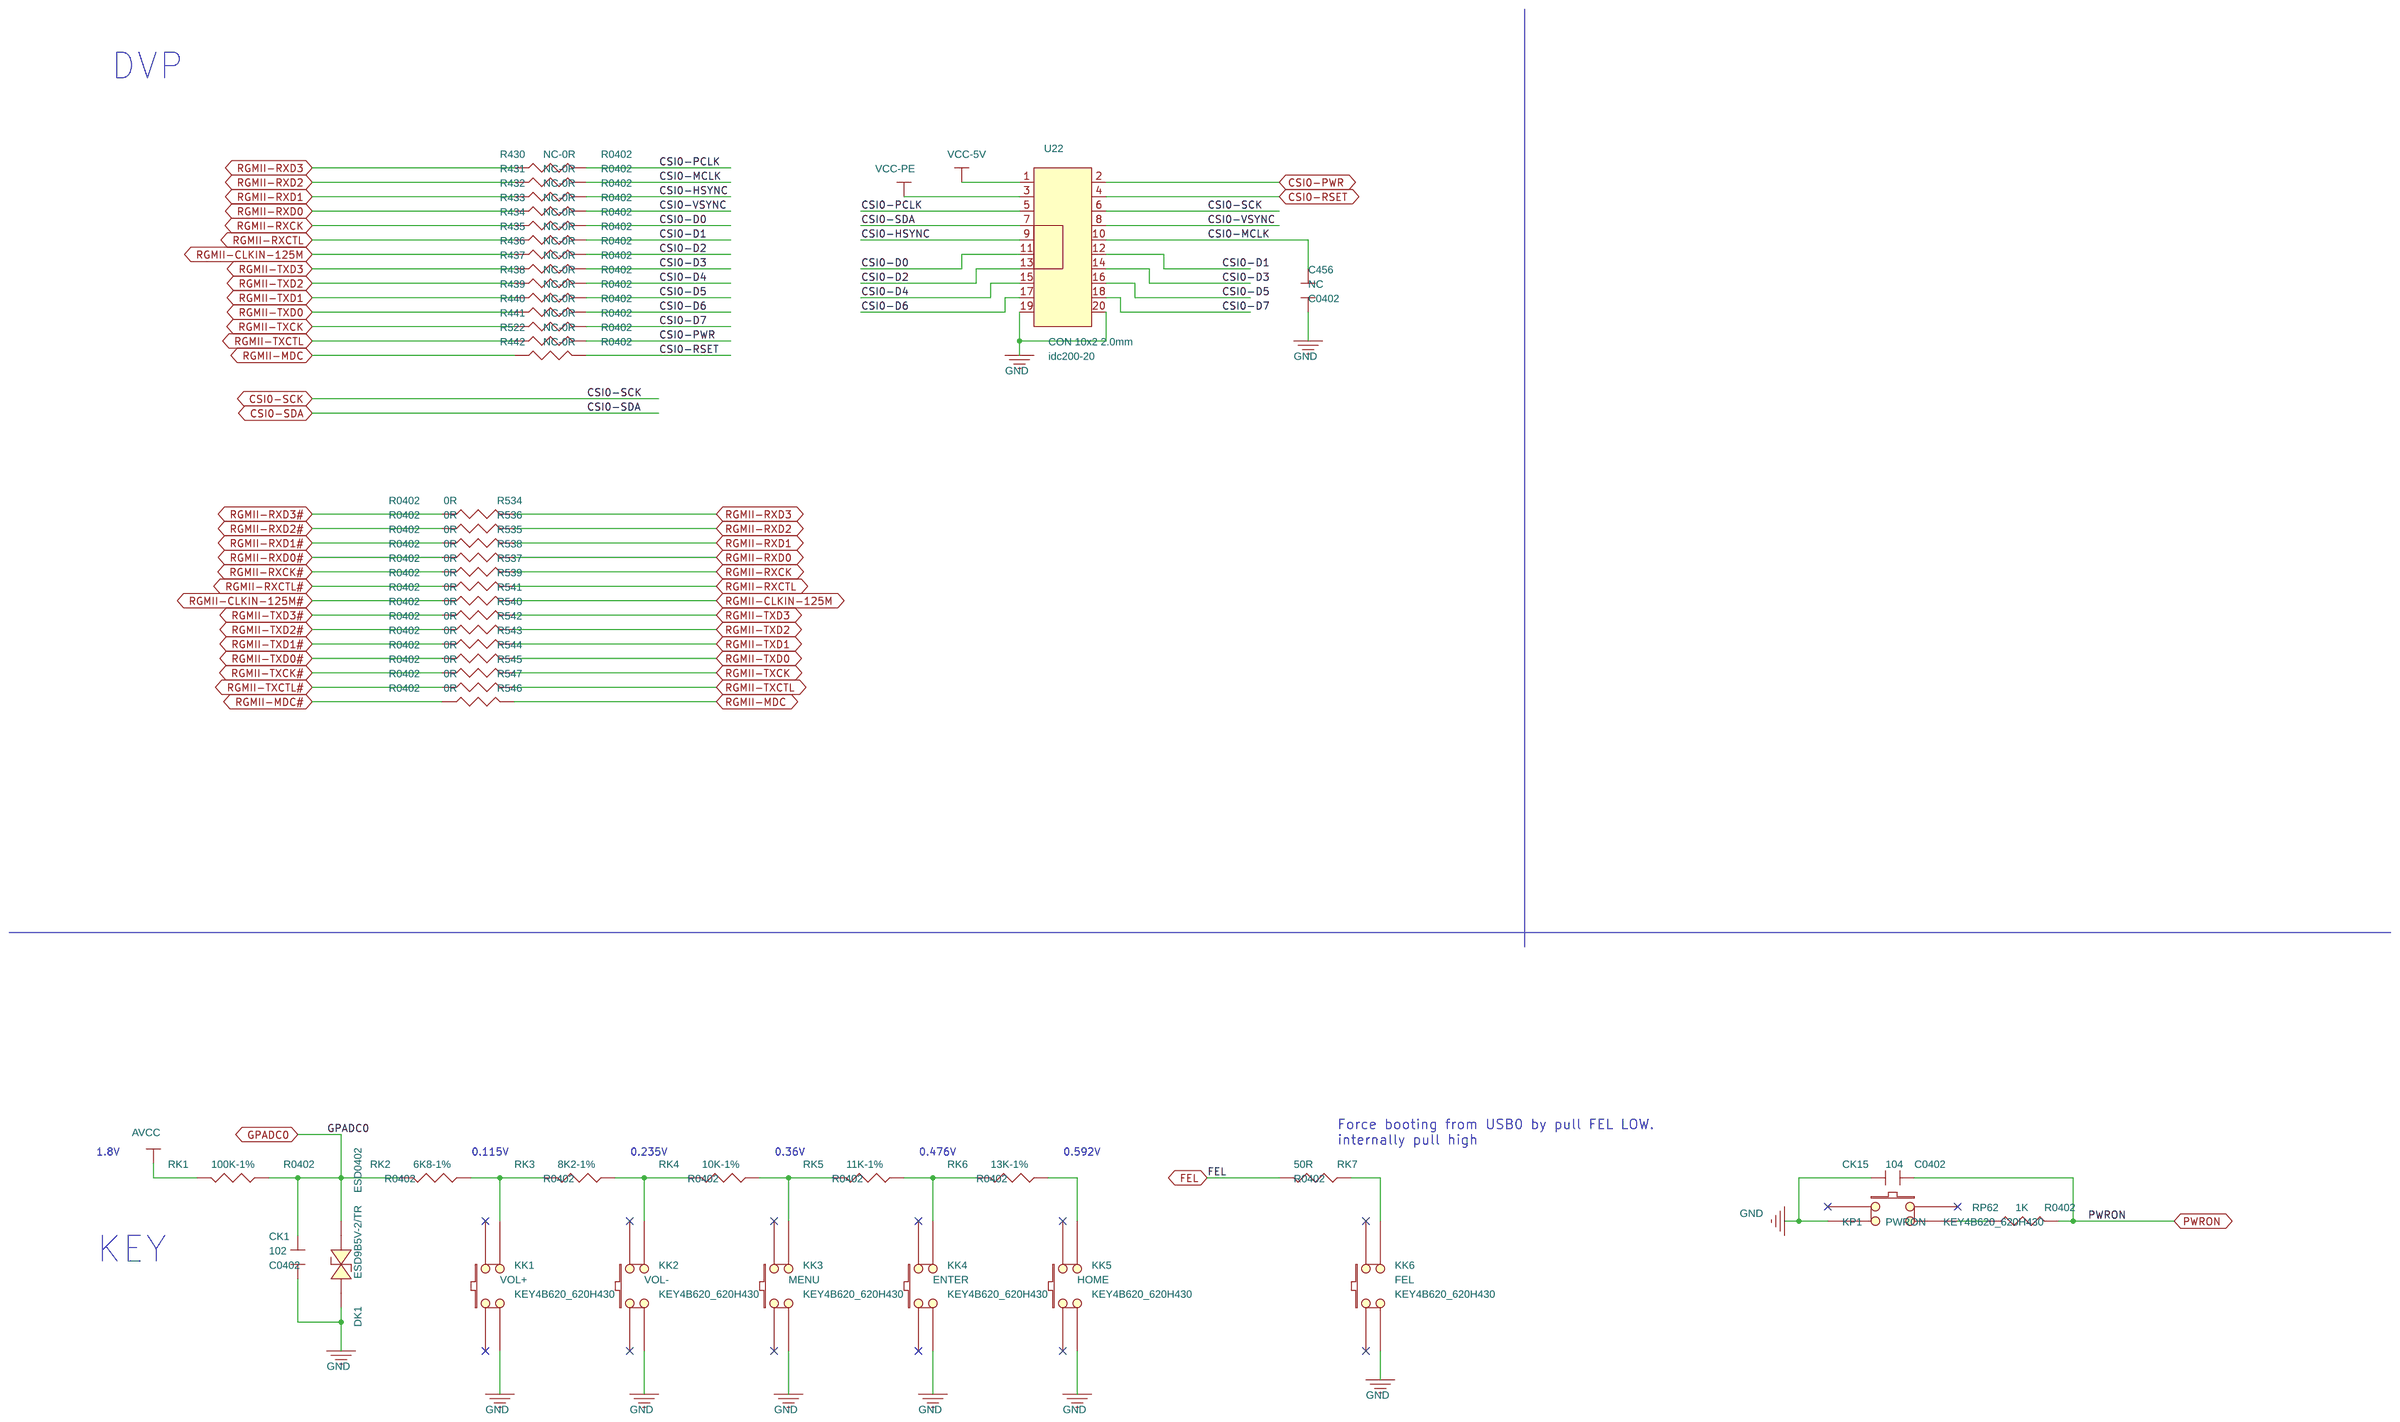
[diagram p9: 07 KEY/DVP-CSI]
11 04 CARD/USB/HUB: size A3; note: CARD/USB
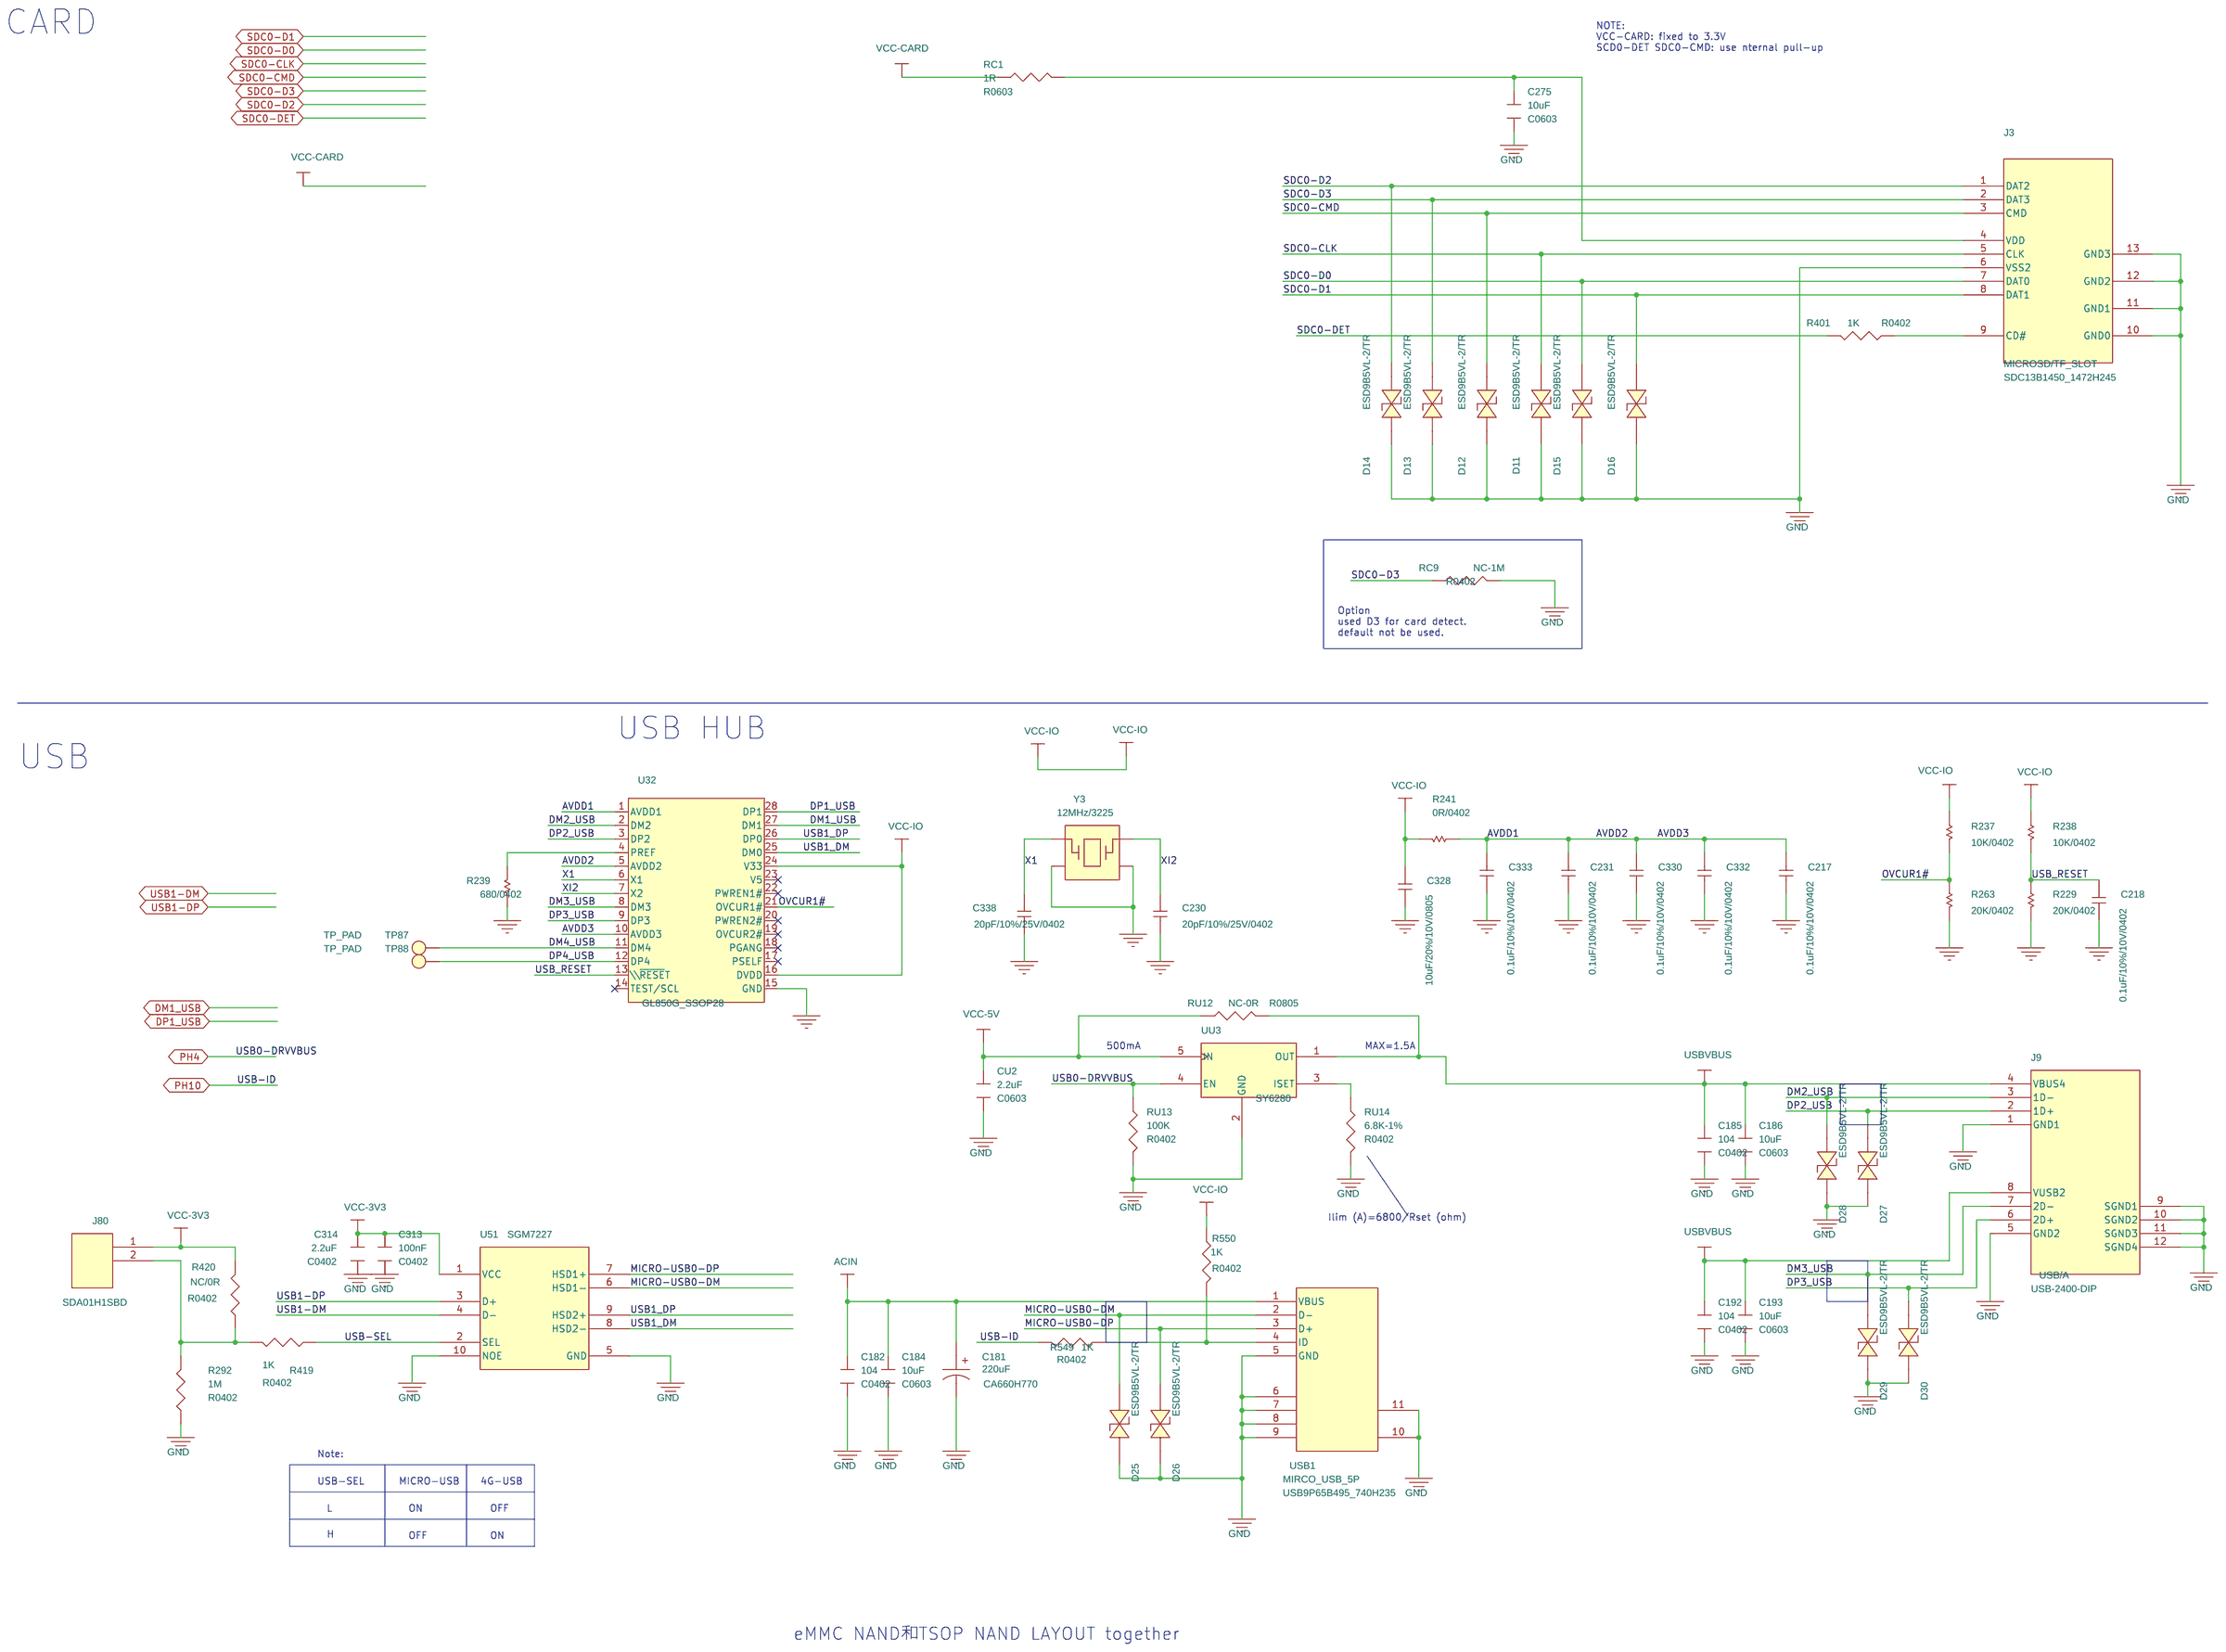
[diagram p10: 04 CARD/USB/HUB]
12 08 RGB/CTP/MIPI-DSI: size A3; note: LCD/DSI/CTP
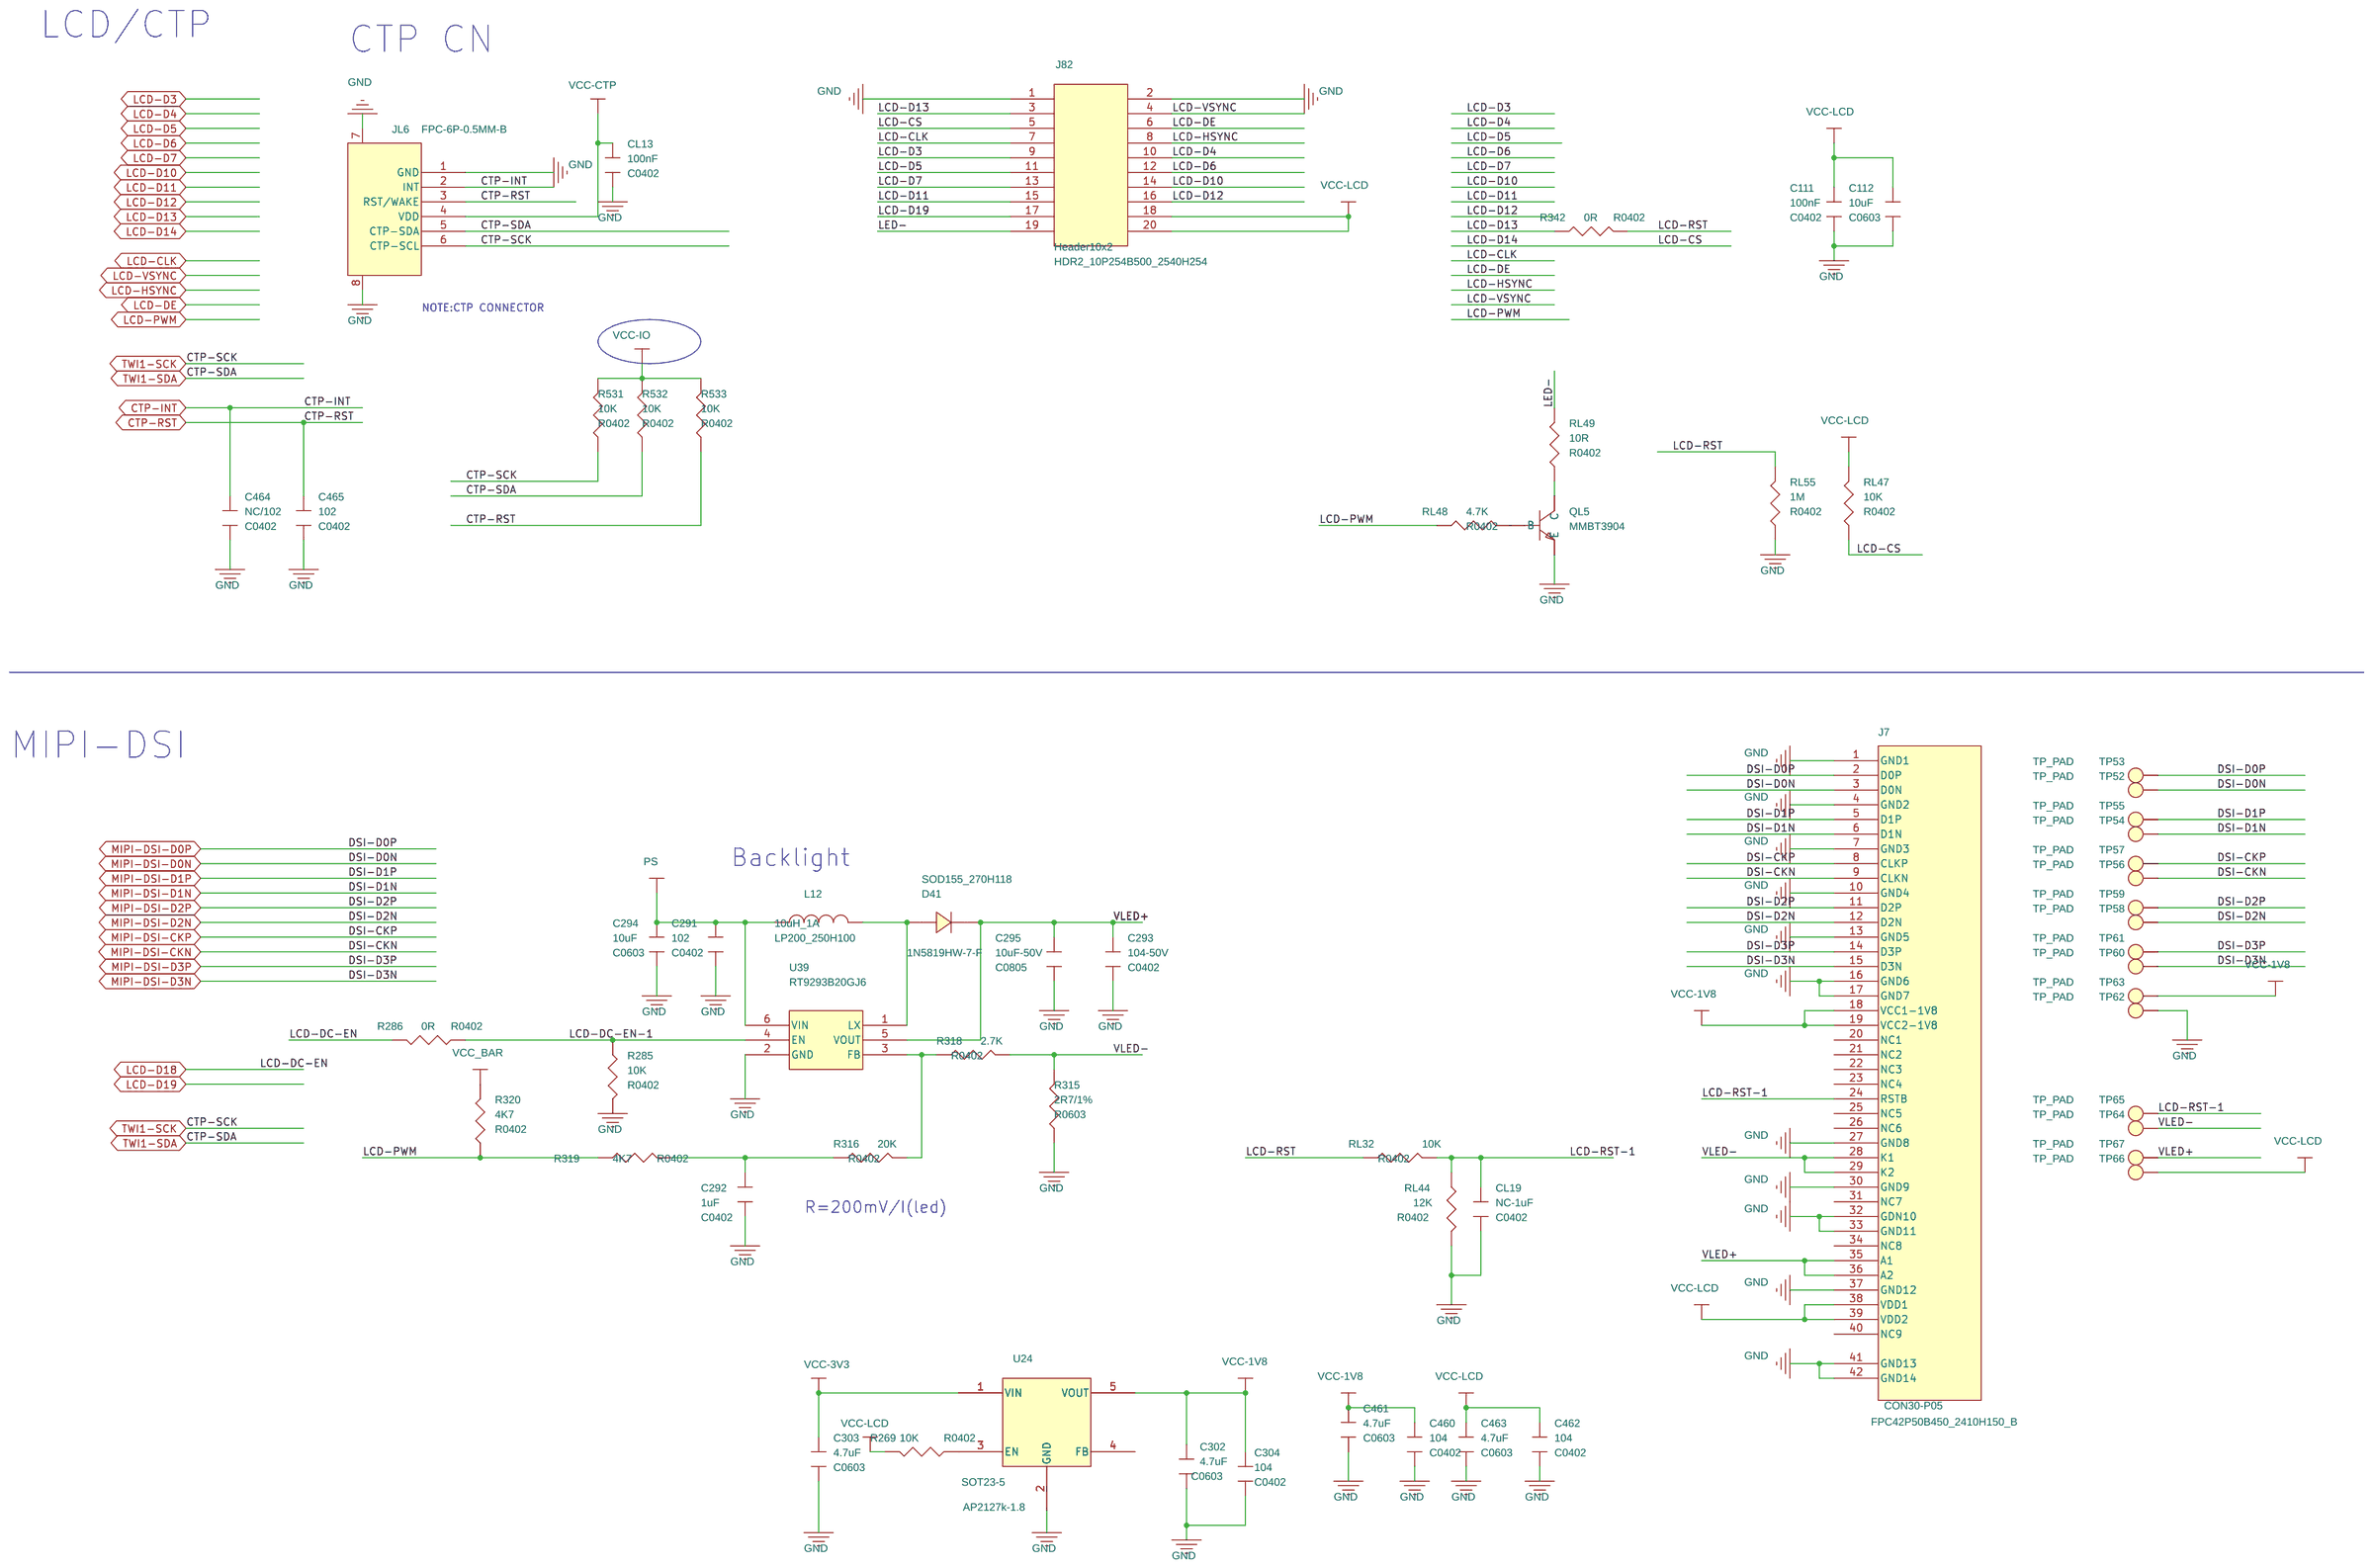
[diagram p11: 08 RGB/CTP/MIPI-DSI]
13 09 LED/G-SENSOR/GPS: size A3; note: LED/G-SENSOR/GPS
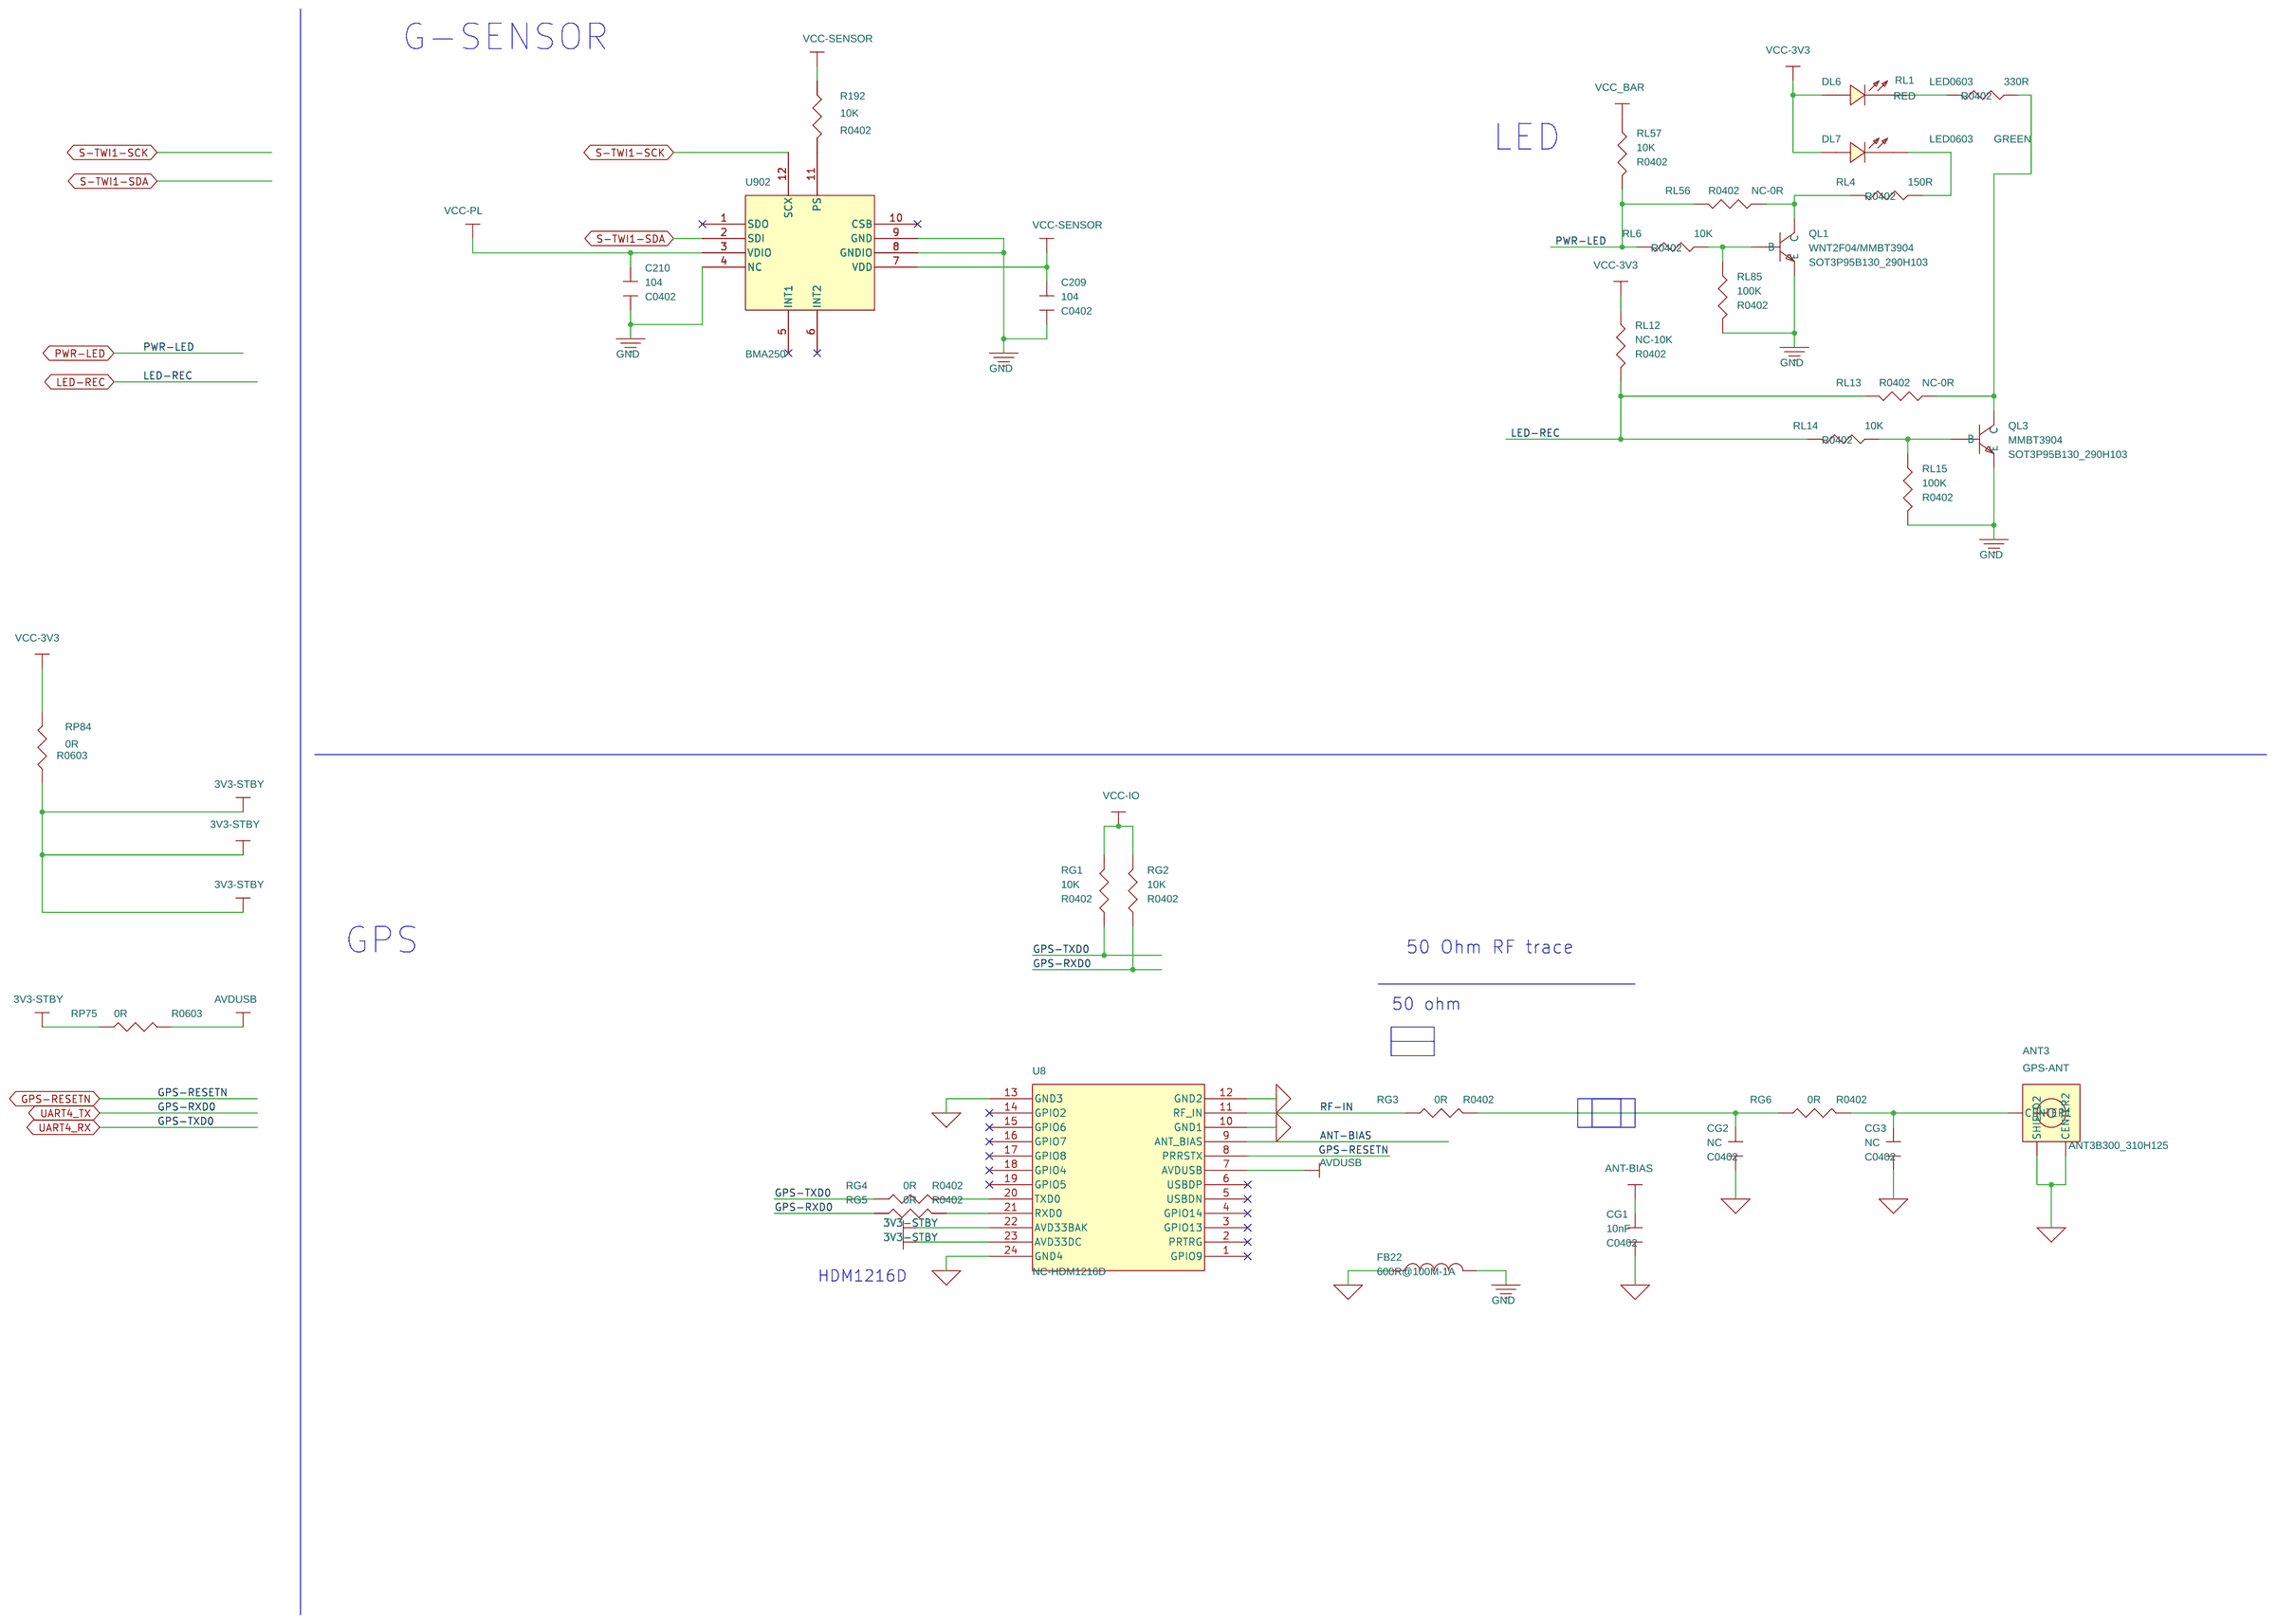
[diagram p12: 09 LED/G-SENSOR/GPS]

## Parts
sheet 01 POWER-AXP2101
C69  104  [C0402]
C70  10uF  [C0603]
C81  4.7uF  [C0603]
C82  104  [C0402]
C84  104  [C0402]
C85  4.7uF  [C0603]
C385  10uF  [C0603]
C471  104  [C0402]
C472  10uF  [C0603]
D7  RB521S-30  [SOD80_120H80]
D608  RB521S-30  [SOD80_120H80]
J1  BATTARY  [HDR1_3P200B670_600H610]
J81  DC-IN-JACK  [DC-208]
R39  1K  [R0402]
R43  10K  [R0402]
R45  62K-1%  [R0402]
R46  54.9K-1%  [R0402]
R548  0R  [R0805]
RP81  0R  [R0402]
RP82  0R  [R0402]
RP85  NC/0R  [R0402]
TP5  GND  [TP_PAD]
TP6  GND  [TP_PAD]
TP7  GND  [TP_PAD]
TP8  GND  [TP_PAD]
TP9  GND  [MH320CIR500D]
TP10  GND  [MH320CIR500D]
TP11  GND  [MH320CIR500D]
TP12  GND  [MH320CIR500D]
U2  AP2127k-ADJ  [SOT5P95B160_300H130]
U3  BAT  [CSE]
sheet 02 V536MODE
U901  V536_MODE  [V536_156PIN]
sheet 03 EMMC
C114  104  [C0402]
C115  104  [C0402]
C116  104  [C0402]
C117  104  [C0402]
RM50  33R  [R0402]
UM2  GB042-34S-H10-Plug  [GB042-34P-H10-PLUG]
sheet 04 CARD/USB/HUB
C181  220uF  [CA660H770]
C182  104  [C0402]
C184  10uF  [C0603]
C185  104  [C0402]
C186  10uF  [C0603]
C192  104  [C0402]
C193  10uF  [C0603]
C217  0.1uF/10%/10V/0402  [C0402]
C218  0.1uF/10%/10V/0402  [C0402]
C230  20pF/10%/25V/0402  [C0402]
C231  0.1uF/10%/10V/0402  [C0402]
C275  10uF  [C0603]
C313  100nF  [C0402]
C314  2.2uF  [C0402]
C328  10uF/20%/10V/0805  [C0805]
C330  0.1uF/10%/10V/0402  [C0402]
C332  0.1uF/10%/10V/0402  [C0402]
C333  0.1uF/10%/10V/0402  [C0402]
C338  20pF/10%/25V/0402  [C0402]
CU2  2.2uF  [C0603]
D11  ESD9B5VL-2/TR  [ESD0402]
D12  ESD9B5VL-2/TR  [ESD0402]
D13  ESD9B5VL-2/TR  [ESD0402]
D14  ESD9B5VL-2/TR  [ESD0402]
D15  ESD9B5VL-2/TR  [ESD0402]
D16  ESD9B5VL-2/TR  [ESD0402]
D25  ESD9B5VL-2/TR  [ESD0402]
D26  ESD9B5VL-2/TR  [ESD0402]
D27  ESD9B5VL-2/TR  [ESD0402]
D28  ESD9B5VL-2/TR  [ESD0402]
D29  ESD9B5VL-2/TR  [ESD0402]
D30  ESD9B5VL-2/TR  [ESD0402]
J3  MICROSD/TF_SLOT  [SDC13B1450_1472H245]
J9  USB/A  [USB-2400-DIP]
J80  SDA01H1SBD  [KEY2B452_749H445]
R229  20K/0402  [R0402]
R237  10K/0402  [R0402]
R238  10K/0402  [R0402]
R239  680/0402  [R0402]
R241  0R/0402  [R0402]
R263  20K/0402  [R0402]
R292  1M  [R0402]
R401  1K  [R0402]
R419  1K  [R0402]
R420  NC/0R  [R0402]
R549  1K  [R0402]
R550  1K  [R0402]
RC1  1R  [R0603]
RC9  NC-1M  [R0402]
RU12  NC-0R  [R0805]
RU13  100K  [R0402]
RU14  6.8K-1%  [R0402]
TP87  TEST POINT SURFACE  [TP_PAD]
TP88  TEST POINT SURFACE  [TP_PAD]
U32  GL850G_SSOP28  [SOP28P65B530_1020H200]
U51  SGM7227  [SOP10P50B300_300H110]
USB1  MIRCO_USB_5P  [USB9P65B495_740H235]
UU3  SY6280  [SOT5P95B160_300H130]
Y3  12MHz/3225  [X4B250_320H80_SMD]
sheet 05 AUDIO
C49  2.2uF  [C0402]
C52  100nF  [C0402]
C56  4.7uF  [C0603]
C58  100nF  [C0402]
C75  4.7uF  [C0603]
C83  NC-33pF  [C0402]
C88  NC-100pF  [C0402]
C89  NC-33pF  [C0402]
C163  4.7uF  [C0603]
C183  NC/4.7uF  [C0603]
C189  334  [C0402]
C194  104  [C0402]
C195  10uF  [C0603]
C196  104  [C0402]
C384  4.7uF  [C0603]
C457  4.7uF  [C0603]
C458  104  [C0402]
C459  104  [C0402]
C468  334  [C0402]
C469  10uF  [C0603]
C470  NC/4.7uF  [C0603]
D10  NC-ESD5451X  [ESD0402]
D35  NC-ESD5451X  [ESD0402]
D39  ESD5451X-2-TR  [ESD0402]
D40  ESD5451X-2-TR  [ESD0402]
D609  ESD5451X  [ESD0402]
D610  ESD5451X  [ESD0402]
FB12  0R  [L0603]
J21  PJ-327F  [HP5B650_1400H500]
J79  HP-JACK  [HP5B650_1400H500]
MIC1  Micphone  [MIC2B600H500]
R19  1K  [R0402]
R20  1.5K  [R0402]
R23  1.5K  [R0402]
R24  1K  [R0402]
R33  4.7K  [R0402]
R40  NC-2K  [R0402]
R41  NC-2K  [R0402]
R174  10K  [R0402]
R177  10K  [R0402]
R178  36K  [R0402]
R179  36K  [R0402]
R180  0R  [R0402]
R181  0R  [R0402]
R182  1K  [R0402]
R183  4K7  [R0402]
R184  3K3  [R0402]
R185  10K  [R0402]
R421  4.7K  [R0402]
R422  4.7K  [R0402]
R423  4.7K  [R0402]
R525  NC-0R  [R0402]
R526  NC-0R  [R0402]
R527  NC-0R  [R0402]
R528  NC-0R  [R0402]
R529  NC-0R  [R0402]
U11  2_54_16P  [HDR2_7P254]
U23  SMG8905  [sop11p50b300_300h110]
sheet 06 HDMI
CH1  104  [C0402]
CH2  104  [C0402]
DH2  ESD5451X  [ESD0402]
DH3  ESD5451X  [ESD0402]
DH4  ESD5451X  [ESD0402]
DH5  ESD5451X  [ESD0402]
DH12  B5819W  [SOD155_270H118]
JH1  HDMI_19plug type A  [HDMI23P50B1215_1500H838]
RH5  1K  [R0402]
RH16  27K-1%  [R0402]
RH17  1.8K  [R0402]
RH18  1.8K  [R0402]
RH19  33R  [R0402]
RH20  33R  [R0402]
RH21  0R  [R0402]
UH1  AZ1345-04F  [RCLAMP0524P]
UH2  AZ1345-04F  [RCLAMP0524P]
sheet 07 KEY/DVP-CSI
C456  NC  [C0402]
CK1  102  [C0402]
CK15  104  [C0402]
DK1  ESD9B5V-2/TR  [ESD0402]
KK1  VOL+  [KEY4B620_620H430]
KK2  VOL-  [KEY4B620_620H430]
KK3  MENU  [KEY4B620_620H430]
KK4  ENTER  [KEY4B620_620H430]
KK5  HOME  [KEY4B620_620H430]
KK6  FEL  [KEY4B620_620H430]
KP1  PWRON  [KEY4B620_620H430]
R430  NC-0R  [R0402]
R431  NC-0R  [R0402]
R432  NC-0R  [R0402]
R433  NC-0R  [R0402]
R434  NC-0R  [R0402]
R435  NC-0R  [R0402]
R436  NC-0R  [R0402]
R437  NC-0R  [R0402]
R438  NC-0R  [R0402]
R439  NC-0R  [R0402]
R440  NC-0R  [R0402]
R441  NC-0R  [R0402]
R442  NC-0R  [R0402]
R522  NC-0R  [R0402]
R534  0R  [R0402]
R535  0R  [R0402]
R536  0R  [R0402]
R537  0R  [R0402]
R538  0R  [R0402]
R539  0R  [R0402]
R540  0R  [R0402]
R541  0R  [R0402]
R542  0R  [R0402]
R543  0R  [R0402]
R544  0R  [R0402]
R545  0R  [R0402]
R546  0R  [R0402]
R547  0R  [R0402]
RK1  100K-1%  [R0402]
RK2  6K8-1%  [R0402]
RK3  8K2-1%  [R0402]
RK4  10K-1%  [R0402]
RK5  11K-1%  [R0402]
RK6  13K-1%  [R0402]
RK7  50R  [R0402]
RP62  1K  [R0402]
U22  CON 10x2 2.0mm  [idc200-20]
sheet 08 RGB/CTP/MIPI-DSI
C111  100nF  [C0402]
C112  10uF  [C0603]
C291  102  [C0402]
C292  1uF  [C0402]
C293  104-50V  [C0402]
C294  10uF  [C0603]
C295  10uF-50V  [C0805]
C302  4.7uF  [C0603]
C303  4.7uF  [C0603]
C304  104  [C0402]
C460  104  [C0402]
C461  4.7uF  [C0603]
C462  104  [C0402]
C463  4.7uF  [C0603]
C464  NC/102  [C0402]
C465  102  [C0402]
CL13  100nF  [C0402]
CL19  NC-1uF  [C0402]
D41  1N5819HW-7-F  [SOD155_270H118]
J7  CON30-P05  [FPC42P50B450_2410H150_B]
J82  Header10x2  [HDR2_10P254B500_2540H254]
JL6  FPC-6P-0.5MM-B  [FPC8P50B320_500H150_B]
L12  10uH_1A  [LP200_250H100]
QL5  MMBT3904  [SOT3P95B130_290H103]
R269  10K  [R0402]
R285  10K  [R0402]
R286  0R  [R0402]
R315  2R7/1%  [R0603]
R316  20K  [R0402]
R318  2.7K  [R0402]
R319  4K7  [R0402]
R320  4K7  [R0402]
R342  0R  [R0402]
R531  10K  [R0402]
R532  10K  [R0402]
R533  10K  [R0402]
RL32  10K  [R0402]
RL44  12K  [R0402]
RL47  10K  [R0402]
RL48  4.7K  [R0402]
RL49  10R  [R0402]
RL55  1M  [R0402]
TP52  TEST POINT SURFACE  [TP_PAD]
TP53  TEST POINT SURFACE  [TP_PAD]
TP54  TEST POINT SURFACE  [TP_PAD]
TP55  TEST POINT SURFACE  [TP_PAD]
TP56  TEST POINT SURFACE  [TP_PAD]
TP57  TEST POINT SURFACE  [TP_PAD]
TP58  TEST POINT SURFACE  [TP_PAD]
TP59  TEST POINT SURFACE  [TP_PAD]
TP60  TEST POINT SURFACE  [TP_PAD]
TP61  TEST POINT SURFACE  [TP_PAD]
TP62  TEST POINT SURFACE  [TP_PAD]
TP63  TEST POINT SURFACE  [TP_PAD]
TP64  TEST POINT SURFACE  [TP_PAD]
TP65  TEST POINT SURFACE  [TP_PAD]
TP66  TEST POINT SURFACE  [TP_PAD]
TP67  TEST POINT SURFACE  [TP_PAD]
U24  AP2127k-1.8  [SOT23-5]
U39  RT9293B20GJ6  [SOT6p95b160_290h145]
sheet 09 LED/G-SENSOR/GPS
ANT3  GPS-ANT  [ANT3B300_310H125]
C209  104  [C0402]
C210  104  [C0402]
CG1  10nF  [C0402]
CG2  NC  [C0402]
CG3  NC  [C0402]
DL6  RED  [LED0603]
DL7  GREEN  [LED0603]
FB22  600R@100M-1A  [L0603]
QL1  WNT2F04/MMBT3904  [SOT3P95B130_290H103]
QL3  MMBT3904  [SOT3P95B130_290H103]
R192  10K  [R0402]
RG1  10K  [R0402]
RG2  10K  [R0402]
RG3  0R  [R0402]
RG4  0R  [R0402]
RG5  0R  [R0402]
RG6  0R  [R0402]
RL1  330R  [R0402]
RL4  150R  [R0402]
RL6  10K  [R0402]
RL12  NC-10K  [R0402]
RL13  NC-0R  [R0402]
RL14  10K  [R0402]
RL15  100K  [R0402]
RL56  NC-0R  [R0402]
RL57  10K  [R0402]
RL85  100K  [R0402]
RP75  0R  [R0603]
RP84  0R  [R0603]
U8  NC-HDM1216D  [DFN24P110B1220_1600H270]
U902  BMA250  [QFN12P50B200_200H100]
sheet 10 WIFI
C167  104  [C0402]
C170  10uF  [C0603]
C466  10uF  [C0603]
C467  104  [C0402]
U12  DIP14_2_0  [hdr2_7p2_00]
U13  DIP16_2_0  [HDR2_8P2_00]
sheet 11 4G-SIM7600CE
ANT2  IPEX  [ANT3B300_310H125]
CL28  22pF  [C0402]
CL29  22pF  [C0402]
CL31  100nF  [C0402]
CL32  33pF  [C0402]
CL46  104  [C0402]
CL47  104  [C0402]
CL48  33pF  [C0402]
CL58  33pF  [C0402]
CL59  10uF  [C0603]
CL60  10uF-16V  [C0603]
CL61  104  [C0402]
CL62  22uF  [C0805]
CL64  NC-27pF  [C0402]
CL65  104-16V  [C0402]
CL66  10uF  [C0603]
CL67  104  [C0402]
CL69  22uF  [C0805]
CL80  10uF  [C0603]
CL81  104  [C0402]
CL82  10uF  [C0603]
CL86  33pF  [C0402]
CL88  104  [C0402]
CL94  104  [C0402]
CW26  NC  [C0402]
CW27  NC  [C0402]
CW30  22pF  [C0402]
DL49  NC/ESD5451X  [ESD0402]
DL50  NC/ESD5451X  [ESD0402]
DL51  NC/ESD5451X  [ESD0402]
DL52  NC/ESD5451X  [ESD0402]
JL26  SIM508C  [sim-6_1]
LP7  2.2uH@3A DCR<0.1R  [LP400_400H120]
OC5  220uF/16V  [CA660H770]
OC6  220uF/16V  [CA660H770]
QL13  MMBT3904  [SOT-23]
RL20  0R  [R0402]
RL23  0R  [R0402]
RL24  22R  [R0402]
RL25  22R  [R0402]
RL38  10K  [R0402]
RL39  2K2-1%  [R0402]
RL40  22R  [R0402]
RL41  0R  [R0402]
RL45  0R  [R0603]
RL69  47K  [R0402]
RL70  4K7  [R0402]
RL84  12K-1%  [R0402]
TP79  TDO  [TP100]
TP80  TDO  [TP100]
TP81  TDO  [TP100]
TP82  TDO  [TP100]
TP83  TDO  [TP100]
TP84  TDO  [TP100]
U27  SIM7600C  [SUB_4G87B3000_3000H290]
UL9  SY8120B1ABC  [SOT6P95B180_310H100]
sheet 12 GMAC
C139  NC/10pF-NPO  [C0402]
C140  NC/10pF-NPO  [C0402]
C206  104  [C0402]
CM7  104  [C0402]
CM8  104  [C0402]
CM9  104  [C0402]
CM10  4.7uF  [C0402]
CM11  NC-22pF  [C0402]
CM12  NC-22pF  [C0402]
CM13  22pF  [C0402]
CM14  104  [C0402]
CM15  NC-100pF  [C0402]
CM16  104  [C0402]
CM17  NC  [C0402]
CM18  10uF  [C0603]
CM19  104  [C0402]
CM20  104  [C0402]
CM21  104  [C0402]
CM22  104  [C0402]
CM23  NC-100pF  [C0402]
CM24  NC-100pF  [C0402]
CM25  NC-104  [C0402]
CM26  NC-104  [C0402]
CM27  104  [C0402]
CM28  104  [C0402]
DM1  POWER  [LED0805]
LM1  2.2uH/1A DCR<0.1R  [LP200_250H100]
Q23  BSN20  [SOT3P95B130_290H103]
R50  2K49 1%  [R0402]
R51  NC/0R  [R0402]
RM2  510R  [R0402]
RM4  0R  [R0603]
RM5  0R*4  [RN0402]
RM7  NC-0R  [R0603]
RM8  0R  [R0402]
RM9  0R  [R0402]
RM12  0R  [R0402]
RM13  0R  [R0402]
RM14  0R  [R0402]
RM15  0R*4  [RN0402]
RM16  1K5  [R0402]
RM17  0R  [R0402]
RM18  4K7  [R0402]
RM19  NC-4K7  [R0402]
RM20  4K7  [R0402]
RM21  4K7  [R0402]
RM22  4K7  [R0402]
RM23  NC-4K7  [R0402]
RM24  NC/4K7  [R0402]
RM25  4K7  [R0402]
RM26  NC-4K7  [R0402]
RM27  4K7  [R0402]
RM28  NC-0R  [R0402]
RM29  4K7  [R0402]
RM30  NC-4K7  [R0402]
RM31  4K7  [R0402]
RM32  NC-4K7  [R0402]
RM33  0R  [R0402]
RM34  510R  [R0402]
RM35  NC-510R  [R0402]
RM36  NC-4K7  [R0402]
RM37  4K7  [R0402]
RM38  4K7  [R0402]
RM39  NC-4K7  [R0402]
RM40  4K7  [R0402]
RM41  NC-4K7  [R0402]
RM42  NC-0R  [R0402]
RM43  0R  [R0402]
RM44  0R  [R0402]
RM45  NC/0R  [R0402]
RM52  0R  [R0402]
RM53  0R  [R0603]
RM54  0R  [R0402]
RM55  510R  [R0402]
RM56  0R  [R0402]
TP71  TEST POINT SURFACE  [TP_PAD]
TP72  TEST POINT SURFACE  [TP_PAD]
TP73  TEST POINT SURFACE  [TP_PAD]
TP74  TEST POINT SURFACE  [TP_PAD]
TP75  TEST POINT SURFACE  [TP_PAD]
TP76  TEST POINT SURFACE  [TP_PAD]
TP77  TEST POINT SURFACE  [TP_PAD]
TP78  TEST POINT SURFACE  [TP_PAD]
TP85  TEST POINT SURFACE  [TP_PAD]
TP86  TEST POINT SURFACE  [TP_PAD]
U19  RMS-086C-10F0-GY  [rj45-hfj11-1g01e]
UM1  RTL8211F-CG  [QFN41P40B500_500H75]
X3  NC/25M-12pF-20PPM  [X4B250_320H80_SMD]
sheet 13 CON
CK16  102  [C0402]
DK2  ESD9B5V-2/TR  [ESD0402]
J11  Header10x2  [HDR2_10P254B500_2540H254]
J12  XH2.54MM-5P-M  [HDR1_5P250B570_1500H700]
J33  CON1X3-2.54-M  [HDR1_3P254B250_762H254]
J35  CON1X4-2.54-M  [HDR1_4P254B250_1016H254]
J36  CON1X4-2.54-M  [HDR1_4P254B250_1016H254]
J56  CON1X3-2.54-M  [HDR1_3P254B250_762H254]
Q2  2N7002  [SOT3P95B130_290H103]
R13  10K  [R0402]
R75  2K  [R0402]
R76  2K  [R0402]
R77  2K  [R0402]
R78  2K  [R0402]
R348  1K  [R0402]
RK8  100K-1%  [R0402]

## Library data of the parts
C69 C81 C82 C84 C85 C182 C184-C186 C192 C193 C206 C275 C302-C304 C385 C471 C472 = CAPACITOR
C70 = CAPACITOR_0: PAGE: 1; ROOM: POWER
D7 = DIODE_SCHOTTKY_0: PAGE: 6
D608 = DIODE_SCHOTTKY_3: PAGE: 6
J1 = CON3: ROOM: POWER
J81 = PHONEJack_DCIN_0: 02 DESC: CONN,  Power Jack F
R39 R43 R45 R46 R50 R51 R192 R401 R531-R533 R548 RH5 RL1 RL4 RL6 RL12-RL15 RL20 RL23-RL25 RL38-RL41 RL45 RL56 RL57 RL84 RL85 RM4 RM7 RM16 RM18-RM27 RM29-RM32 RM36-RM41 RM45 RM52 RM53 RM56 = R_v2
RP81 RP82 RP85 = R-R0603-5%
TP5-TP12 TP52-TP67 TP71-TP88 = TEST_POINT_SURFACE
U2 U24 = uP0107_0
U3 = BAT_0: PAGE: 6
U901 = A10_MODE_20: RoHS A10_MODE核心板PCB
C114-C117 = CAPACITOR_0: PAGE: 2; mypage: 08
RM50 = R-R0402-5%: mypage: 08
UM2 = NAND_FLASH_TSOP48_1
C181 = CAPACITOR_POL_0: ROOM: POWER
C217 C218 C231 C330 C332 C333 = C: ATHEROS KEY: 031-104CK-002; AtherosDescription: CAP,0402,X5R,0.1uF,+/-10%,10V; CISPartType: Capacitor\0402; StandardCost-100K: 0; Tolerance: +/-10%; URL: 0; VendorDescription: CAP, MLCC, X5R, 0.1uF +/-10%, 10V, 0402, 7"T+R; VendorName: Yageo; VendorPartNumber: CC0402KRX5R6BB104; Voltage: 10V
C230 C338 = C: ATHEROS KEY: 031-XXXXX-000; AtherosDescription: CAP,0402,No_Load; CISPartType: Capacitor\0402; StandardCost-100K: 0; URL: 0; VendorDescription: CAP, MLCC, X5R, 0.1uF +/-10%, 10V, 0402, 7"T+R; VendorName: Yageo; VendorPartNumber: CC0402KRX5R6BB104
C49 C52 C56 C58 C83 C88 C89 C313 C314 = C-C0402
C328 = C: ATHEROS KEY: 033-106CK-001; AtherosDescription: CAP,0805,X5R,10uF,10%,6.3V; CISPartType: Capacitor\0805; Tolerance: +/-10%; Voltage: 6.3V
C75 C384 CK15 CU2 = C-C0603
D11-D16 = 1_1.5KE100A: 1ST PART DESCRIPTION: WILL ESD9B5V Bidirection ESD Protection; Page: 11
D25-D30 D609 D610 DH2-DH5 DL49-DL52 = 1_1.5KE100A: 1ST PART DESCRIPTION: WILL ESD9B5V Bidirection ESD Protection
J3 = SDMMC_SLOT_0
J9 = USB_A_4
J80 = CON1X4-2_1.54-M
R229 R237-R239 R241 R263 = R: ATHEROS KEY: 051-XXXXX-000; AtherosDescription: RES,0402,No_Load; CISPartType: Resistor\0402
R13 R19 R20 R23 R24 R33 R40 R41 R75-R78 R292 R342 R348 R419-R423 R430-R442 R522 R525-R529 R534-R547 R549 R550 RC1 RC9 RH17-RH21 RU13 RU14 = R-R0402-5%
RU12 = R-R0805-5%
U32 = GL850G_SSOP28
U51 = SGM7227: parameter: MSOP10
USB1 = USB_MINI_SOCKET_0: USB JACK ROHS
UU3 = SY6280
Y3 = XTAL-4P
C163 C457-C459 CL46-CL48 CL58 CL59 CL80-CL82 CL86 CM18 = CAPACITOR_0
C183 C470 = CAPACITOR: PAGE: 2; mypage: 13
C189 C194-C196 C468 C469 CH1 CH2 = CAPACITOR_0: PAGE: 1
D10 D35 = ESD9B5VL
D39 D40 = ESD5451X
FB12 = INDUCTOR_4
J21 = PJ-327F
J79 = HP_JACK
MIC1 = Micphone_0: mypage: 13
R174 R177-R185 = R_v2: mypage: 13
U11 = NAND_FLASH_TSOP48_9
U23 = SSM2402_SO_2
DH12 = DIO-B5819W
JH1 = HDMI19_PLUG
RH16 = R-R0402-1%
UH1 UH2 = rRClamp0524P
C139 C140 C167 C170 C209 C210 C291-C295 C456 C466 C467 CL28 CL29 CL31 CL32 CW26 CW27 CW30 = CAPACITOR_0: PAGE: 2
CG1-CG3 CK1 CK16 CL13 CL19 CM11-CM14 CM16 CM19-CM22 = C-C0402: PAGE: 2; ROOM: EMMC; mypage: 08
DK1 DK2 = TVS-FBP-02C
KK1-KK6 = SWITCH_PUSH
KP1 = SW_PUSH_5
R269 RK1-RK8 RM2 RM8 RM9 RM12-RM14 RM17 RM28 RM33-RM35 RM42-RM44 RM54 RM55 = R-R0402: ROOM: EMMC; mypage: 08
RP62 = R-R0402
U22 = CON_10x2_2.0mm
C111 C112 = CAPACITOR_0: Page: 10; mypage: 09
C460-C465 = CAPACITOR: ROOM: POWER
D41 = D_0: Allegro PCB Footprint: d2513A
J7 = CON40-B070EW01_0: ROOM: LVDS
J11 J82 = Header10x2
JL6 = FPC-6P-0_0.5MM-B
L12 = INDUCTOR: RoHS Power Inductor 22uH 300mA H<1.8MM,CD32
QL5 = NPN-MMBT3904
R285 R315 R316 R318-R320 RL69 RL70 = RESISTOR
R286 = RESISTOR: NC
RL32 RL44 RL47-RL49 RL55 = R-R0402-5%: ROOM: EMMC; mypage: 08
U39 = RT9293B
ANT3 = SMA_RF_1
DL6 DL7 = LED_0: PAGE: 1
FB22 = INDUCTOR: SIGNAL_MODEL: DEFAULT_INDUCTOR_0.001nH_1_2
QL1 QL3 QL13 = NPN
RG1-RG6 = R_v2: ROOM: TCARD
RP75 RP84 = R-R0603-1%
U8 = FEB1216
U902 = BMA222
U12 = HDR11X2_1
U13 = HDR11X2_2
ANT2 = ANT_0: WIFI_ANT
CL60-CL62 CL64-CL67 CL69 CL88 CL94 = CAPACITOR_1: PAGE: 1
JL26 = SDMMC_SLOT_5
LP7 = INDUCTOR_1
OC5 OC6 = CAPACITOR_POL_0
U27 = AP1511B_2: page: 9
UL9 = SY8088_0
CM7-CM10 CM15 CM17 CM23-CM28 = CAP_2: ROOM: EMAC
DM1 = LED_3: PAGE: 1
LM1 = L-LP2_00X1_60H1_00
Q23 = NMOS-BSN20
RM5 RM15 = R-PACK4_1
U19 = HFJ11-1G01E_2
UM1 = RTL8169s_1
X3 = CRYSTAL-4_0: Crystal 24MHz 20pF 10ppm  -30 to +85; PART NUMBER: 7M24000004; SPREADWIN PN: U3000019A; Vendor: TXC
J12 = XH2.54MM-5P-M
J33 J56 = CON1X4-2_0.54-M
J35 J36 = CON1X4-2.54-M
Q2 = NMOS-2N7002

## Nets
3V3-STBY: RP75.1 RP84.1 U8.22(AVD33BAK) U8.23(AVD33DC)
AVDD1: C217.2 C231.2 C330.2 C332.2 C333.2 R241.1 U32.1(AVDD1) U32.5(AVDD2) U32.10(AVDD3)
AVDD10: CM20.1 CM21.1 CM22.1 RM44.1 UM1.3(AVDD10) UM1.8(AVDD10) UM1.38(AVDD10)
AVDD33: CM27.2 CM28.2 RM4.1 UM1.11(AVDD33) UM1.40(AVDD33)
DVDD10: CM16.1 RM43.1 UM1.21(DVDD10)
DVDD33: CM8.2 CM9.2 RM20.2 RM21.2 RM27.1 RM30.1 RM32.1 RM34.1 RM52.1 RM53.1 UM1.29(DVDD33)
DVDDRG: CM7.2 CM10.2 CM25.2 CM26.2 RM7.1 RM16.2 RM19.1 RM23.1 RM25.1 RM37.1 RM39.1 RM41.1 RM52.2 UM1.28(DVDD_RG)
GND: ANT2.1 ANT2.2 C49.2 C69.1 C70.1 C81.1 C82.1 C83.2 C84.1 C85.1 C89.1 C111.2 C112.2 C114.1 C115.1 C116.1 C117.1 C139.1 C140.1 C163.1 C167.2 C170.2 C181.2 C182.1 C184.1 C185.1 C186.1 C189.2 C192.1 C193.1 C194.2 C195.2 C196.2 C206.2 C209.1 C210.1 C217.1 C218.1 C230.1 C231.1 C275.1 C291.1 C292.1 C293.1 C294.1 C295.1 C302.1 C303.1 C304.1 C313.1 C314.1 C328.2 C330.1 C332.1 C333.1 C338.2 C385.1 C456.2 C457.1 C458.1 C459.1 C460.1 C461.1 C462.1 C463.1 C464.1 C465.1 C466.2 C467.2 C469.2 C471.1 C472.1 CH1.2 CH2.2 CK1.1 CK15.2 CK16.1 CL13.2 CL19.2 CL28.2 CL29.2 CL31.2 CL32.2 CL46.1 CL47.1 CL48.1 CL58.1 CL59.1 CL60.2 CL61.2 CL62.2 CL65.2 CL66.2 CL67.2 CL69.2 CL80.1 CL81.1 CL82.1 CL86.1 CL94.2 CM7.1 CM8.1 CM9.1 CM10.1 CM11.2 CM12.2 CM13.2 CM14.2 CM15.1 CM16.2 CM17.1 CM18.1 CM19.2 CM20.2 CM21.2 CM22.2 CM23.1 CM24.1 CM25.1 CM26.1 CM27.1 CM28.1 CU2.1 CW26.2 CW27.2 CW30.2 D10.1(ANODE) D11.2(CATHODE) D12.2(CATHODE) D13.2(CATHODE) D14.2(CATHODE) D15.2(CATHODE) D16.2(CATHODE) D25.2(CATHODE) D26.2(CATHODE) D27.2(CATHODE) D28.2(CATHODE) D29.2(CATHODE) D30.2(CATHODE) D35.1(ANODE) D39.1(ANODE) D40.1(ANODE) D609.1(ANODE) D610.1(ANODE) DH2.2(CATHODE) DH3.2(CATHODE) DH4.2(CATHODE) DH5.2(CATHODE) DK1.1(ANODE) DK2.1(ANODE) DL49.1(ANODE) DL50.1(ANODE) DL51.1(ANODE) DL52.1(ANODE) FB22.2 J1.3 J3.6(VSS2) J3.10(GND0) J3.11(GND1) J3.12(GND2) J3.13(GND3) J7.1(GND1) J7.4(GND2) J7.7(GND3) J7.10(GND4) J7.13(GND5) J7.16(GND6) J7.17(GND7) J7.27(GND8) J7.30(GND9) J7.32(GDN10) J7.33(GND11) J7.37(GND12) J7.41(GND13) J7.42(GND14) J9.1(GND1) J9.5(GND2) J9.9(SGND1) J9.10(SGND2) J9.11(SGND3) J9.12(SGND4) J11.9 J11.10 J11.11 J11.12 J11.13 J11.14 J11.19 J12.1 J12.2 J21.5(A) J33.3 J35.1 J36.1 J56.3 J79.5(A) J81.2(GND0) J81.3(GND1) J82.1 J82.2 JH1.2(G_D2) JH1.5(G_D1) JH1.8(G_D0) JH1.11(G_CLK) JH1.17(G_DDC/CEC) JH1.20(SHIELD1) JH1.21(SHIELD2) JH1.22(SHIELD3) JH1.23(SHIELD4) JL6.1(GND) JL6.7 JL6.8 JL26.7(GND1) JL26.8(GND2) JL26.9(GND3) JL26.10(GND4) JL26.C5(GND) KK1.2 KK2.2 KK3.2 KK4.2 KK5.2 KK6.2 KP1.2 OC5.2 OC6.2 QL1.2(E) QL3.2(E) QL5.2(E) QL13.2(E) R24.2 R46.1 R50.2 R184.1 R185.2 R229.2 R239.1 R263.2 R285.2 R292.1 R315.2 R421.2 R423.2 RC9.2 RL15.2 RL39.1 RL44.1 RL55.1 RL69.2 RL85.2 RM2.1 RM18.2 RM22.2 RM24.2 RM26.2 RM29.2 RM31.2 RM35.2 RM36.2 RM38.2 RM40.2 RM55.1 RU13.2 RU14.2 TP5.1(TP) TP6.1(TP) TP7.1(TP) TP8.1(TP) TP9.1(TP) TP10.1(TP) TP11.1(TP) TP12.1(TP) TP62.1(TP) TP82.1(TP) U2.2(GND) U3.2(+) U11.3 U11.9 U11.10 U11.13 U12.1(GND) U12.5(GND1) U12.12(GND2) U13.9(GND) U13.10(GND1) U13.15(GND2) U13.16(GND3) U19.10(GND) U19.15(GND1) U19.16(GND2) U22.19 U22.20 U23.11(GND) U24.2(GND) U27.1(GND) U27.2(GND1) U27.5(GND2) U27.10(GND3) U27.14(GND4) U27.37(GND6) U27.40(GND7) U27.41(GND8) U27.43(GND9) U27.57(GND10) U27.58(GND11) U27.60(GND12) U27.61(GND13) U27.64(GND14) U27.65(GND15) U27.77(GND16) U27.78(GND17) U27.80(GND18) U27.81(GND5) U32.15(GND) U39.2(GND) U51.5(GND) U51.10(NOE) U901.41(GND6) U901.42(GND7) U901.43(GND8) U901.44(GND9) U901.45(GND10) U901.46(GND11) U901.47(GND12) U901.87(GND13) U901.109(GND15) U901.110(GND16) U901.111(GND17) U901.112(GND18) U901.113(GND19) U901.114(GND20) U901.115(GND21) U901.122(GND22) U901.135(GND23) U901.146(GND24) U902.4(NC) U902.8(GNDIO) U902.9(GND) UH1.3(GND1) UH1.8(GND2) UH2.3(GND1) UH2.8(GND2) UL9.2(GND) UM1.41(EGND) UM2.1 UM2.3 UM2.5 UM2.7 UM2.9 UM2.11 UM2.14 UM2.24 UM2.26 UM2.28 UM2.30 UM2.32 UM2.34 USB1.5(GND) USB1.6 USB1.7 USB1.8 USB1.9 USB1.10 USB1.11 UU3.2(GND) X3.2(GND1) X3.4(GND2) Y3.2 Y3.4
GND_SIGNAL: ANT3.1(CENTER2) ANT3.2(SHIELD2) CG1.1 CG2.1 CG3.1 FB22.1 U8.10(GND1) U8.12(GND2) U8.13(GND3) U8.24(GND4)
VBAT: C69.2 C70.2 J1.1 J11.5 J11.7 U901.30(VBAT1) U901.31(VBAT2)
VCC33-AUDIO: C196.1 C469.1 FB12.2 R183.1 U23.7(PVDD)
VCC-1V8: C302.2 C304.2 C460.2 C461.2 J7.18(VCC1-1V8) J7.19(VCC2-1V8) TP63.1(TP) U24.5(VOUT)
VCC-3V3: C114.2 C115.2 C116.2 C117.2 C163.2 C167.1 C194.1 C195.1 C209.2 C303.2 C313.2 C314.2 C328.1 C459.2 C466.1 DH12.1 DL6.1(ANODE) DL7.1(ANODE) FB12.1 J11.6 J11.8 J36.2 J80.1 Q2.1(G) R13.2 R39.1 R40.1 R41.1 R75.2 R76.2 R192.1 R237.1 R238.1 R241.2 R420.2 R531.2 R532.2 R533.2 R550.1 RC1.1 RG1.2 RG2.2 RL12.1 RL57.1 RM4.2 RM7.2 RM53.2 RP82.2 RP84.2 U11.14 U12.13(VCC) U12.14(VCC1) U24.1(VIN) U32.16(DVDD) U32.24(V33) U51.1(VCC) U901.50(3V3_1) U901.51(3V3_2) U902.7(VDD) UM2.20 UM2.21 UM2.22 UM2.23
VCC-5V: C181.1 C182.2 C184.2 C457.2 C458.2 C471.2 C472.2 CH2.1 CL60.1 CL65.1 CU2.2 J11.1 J11.3 JH1.18(+5V) R548.1 RH17.1 RH18.1 RU12.1 U11.8 U22.1 U901.33(ACIN1) U901.34(ACIN2) UL9.5(IN) USB1.1(VBUS) UU3.5(IN)
VCC-PE: RP82.1 RP85.1 U22.3
VCC-RTC: C84.2 C385.2 D608.2 J11.20 U901.32(RTC)
VCC-WIFI-IO: C170.1 C467.1 RP81.1 U13.14(IOVCC)
4G-STATUS: U27.49(STATUS) U901.105(4G_STATUS)
ALDO1: CL47.2 CL58.2 CL59.2 J11.16 RK1.2 RK8.2 U27.15(VDD_1V8) U901.38(ALDO1)
ALDO3: C210.2 CL13.1 J11.17 J35.2 JL6.4(VDD) Q23.1(G) R77.2 R78.2 U901.39(ALDO3) U902.3(VDIO)
ANT-BIAS: CG1.2 U8.9(ANT_BIAS)
AP-WAKE-4G: U27.72(DTR) U901.108(AP_WAKE_4G)
AP-WAKE-BT: R528.2 U13.13(AP-WAKE-BT) U901.155(AP_WAKE_BT)
AUDIO-L: D609.2(CATHODE) J79.4(D) R180.2
AUDIO-R: D610.2(CATHODE) J79.2(B) R181.1
AVDUSB: RP75.2 U8.7(AVDUSB)
BATT-VCC-3V3: C85.2 D7.2 R43.2 U2.1(VIN) U3.1(-)
BATT-VCC-RTC: C81.2 C82.2 D608.1 R45.2 U2.5(VOUT)
BB-PWREN: RL70.2 U901.107(BB_PWREN)
BB_PW: RL38.2 U901.121(BB_PW)
BLDO1: J11.18 RP81.2 RP85.2 U901.40(BLDO1)
BT-RST-N: R526.2 U13.12(BT-RST-N) U901.156(BT_RST_N)
BT-UART-CTS: U13.6(CTS) U901.1(BT_UART_CTS)
BT-UART-RTS: R525.2 U13.8(RTS) U901.2(BT_UART_RTS)
BT-UART-RX: U13.2(RX) U901.9(BT_UART_RX)
BT-UART-TX: U13.4(TX) U901.8(BT_UART_TX)
BT-WAKE-AP: U13.11(BT-WAKE-AP) U901.120(BT_WAJE_AP)
CLKOUT-125M: RM14.1 UM1.35(CLKOUT)
CSI0-D0: R434.2 U22.11
CSI0-D1: R435.2 U22.12
CSI0-D2: R436.2 U22.13
CSI0-D3: R437.2 U22.14
CSI0-D4: R438.2 U22.15
CSI0-D5: R439.2 U22.16
CSI0-D6: R440.2 U22.17
CSI0-D7: R441.2 U22.18
CSI0-HSYNC: R432.2 U22.9
CSI0-MCLK: C456.1 R431.2 U22.10
CSI0-PCLK: R430.2 U22.5
CSI0-PWR: R522.2 U22.2
CSI0-RSET: R442.2 U22.4
CSI0-SCK: U22.6 U901.28(CSI0_SCK)
CSI0-SDA: U22.7 U901.27(CSI0_SDA)
CSI0-VSYNC: R433.2 U22.8
CTP-INT: C464.2 JL6.2(INT) U901.117(CTP_INT)
CTP-RST: C465.2 JL6.3(RST/WAKE) R533.1 U901.116(CTP_RST)
DC1SW: C111.1 C112.1 C462.2 C463.2 J7.38(VDD1) J7.39(VDD2) J11.15 J82.18 J82.20 R269.2 R320.2 RL47.2 TP66.1(TP) U901.37(VCC_LCD)
DM1_USB: U27.12(USB_DN) U32.27(DM1)
DM2_USB: D28.1(ANODE) J9.3(1D-) U32.2(DM2)
DM3_USB: D29.1(ANODE) J9.7(2D-) U32.8(DM3)
DM4_USB: TP87.1(TP) U32.11(DM4)
DP1_USB: U27.13(USB_DP) U32.28(DP1)
DP2_USB: D27.1(ANODE) J9.2(1D+) U32.3(DP2)
DP3_USB: D30.1(ANODE) J9.6(2D+) U32.9(DP3)
DP4_USB: TP88.1(TP) U32.12(DP4)
EPHY-CLK-25M: RM56.2 U901.24(EPHY_CLK_25M)
FEL: RK7.2 U901.95(FEL)
GPADC0: CK1.2 DK1.2(CATHODE) J33.1 RK1.1 RK2.2 U901.97(GPADC0)
GPADC1: CK16.2 DK2.2(CATHODE) J33.2 RK8.1 U901.96(GPADC1)
GPS-RESETN: R529.2 U8.8(PRRSTX) U901.57(GPS_RST)
HCEC: RH21.1 U901.133(HCEC)
HDMI-CEC: DH5.1(ANODE) JH1.13(CEC) RH16.2 RH21.2
HDMI-SCL: DH4.1(ANODE) JH1.15(SCL) RH17.2 RH19.2
HDMI-SDA: DH3.1(ANODE) JH1.16(SDA) RH18.2 RH20.2
HHPD: CH1.1 RH5.1 U901.134(HHPD)
HSCL: RH19.1 U901.131(HSCL)
HSDA: RH20.1 U901.132(HSDA)
HTX0N: JH1.9(D0N) U901.125(HTX0N) UH2.2(IN2) UH2.9(OUT2)
HTX0P: JH1.7(D0P) U901.126(HTX0P) UH2.1(IN1) UH2.10(OUT1)
HTX1N: JH1.6(D1N) U901.127(HTX1N) UH1.5(IN4) UH1.6(OUT4)
HTX1P: JH1.4(D1P) U901.128(HTX1P) UH1.4(IN3) UH1.7(OUT3)
HTX2N: JH1.3(D2N) U901.129(HTX2N) UH1.2(IN2) UH1.9(OUT2)
HTX2P: JH1.1(D2P) U901.130(HTX2P) UH1.1(IN1) UH1.10(OUT1)
HTXCN: JH1.12(CLKN) U901.123(HTXCN) UH2.5(IN4) UH2.6(OUT4)
HTXCP: JH1.10(CLKP) U901.124(HTXCP) UH2.4(IN3) UH2.7(OUT3)
I2S2-BCLK: R527.1 U11.6
I2S2-DIN: R528.1 U11.7
I2S2-DOUT: R529.1 U11.12
I2S2-LRCK: R526.1 U11.5
I2S2-MCLK: R525.1 U11.4
INTB: RM20.1 UM1.31(INTB/PMEB)
LCD-CLK: J82.7 U901.70(LCD_CLK)
LCD-D3: J82.9 U901.58(LCD_D3)
LCD-D4: J82.10 U901.68(LCD_D4)
LCD-D5: J82.11 U901.63(LCD_D5)
LCD-D6: J82.12 U901.67(LCD_D6)
LCD-D7: J82.13 U901.66(LCD_D7)
LCD-D10: J82.14 U901.64(LCD_D10)
LCD-D11: J82.15 U901.69(LCD_D11)
LCD-D12: J82.16 U901.60(LCD_D12)
LCD-D13: J82.3 R342.1 U901.59(LCD_D13)
LCD-D14: J82.5 RL47.1 U901.62(LCD_D14)
LCD-D18: R286.2 U901.65(LCD_D18)
LCD-D19: J82.17 U901.61(LCD_D19)
LCD-DC-EN-1: R285.1 R286.1 U39.4(EN)
LCD-DE: J82.6 U901.73(LCD_DE)
LCD-HSYNC: J82.8 U901.72(LCD_HSYNC)
LCD-PWM: R319.1 R320.1 RL48.1 U901.74(LCD_PWM)
LCD-RST: R342.2 RL32.1 RL55.2
LCD-RST-1: CL19.1 J7.24(RSTB) RL32.2 RL44.2 TP65.1(TP)
LCD-VSYNC: J82.4 U901.71(LCD_VSYNC)
LED0/CFG-EXT: CM15.2 RM26.1 RM27.2 RM28.2 RM33.2 UM1.32(LED0/CFG_EXT)
LED1/CFG-LDO0: CM24.2 RM29.1 RM30.2 TP85.1(TP) U19.14(Y+) UM1.33(LED1/CFG_LDO0)
LED2/CFG-LDO1: CM23.2 RM31.1 RM32.2 TP86.1(TP) U19.11(G+) UM1.34(LED2/CFG_LDO1)
LED-: J82.19 RL49.2
LED-REC: RL12.2 RL13.2 RL14.2 U901.54(LED_REC)
LINEINL: C75.1 U901.93(LINEINL)
LINEINR: C384.1 U901.94(LINEINR)
LINEOUTL: C183.2 U901.91(LINEOUTL)
LINEOUTR: C470.1 U901.92(LINEOUTR)
MBIAS: C49.1 R19.2 U901.88(MBIAS)
MDC: RM8.1 UM1.13(MDC)
MDI0+: TP77.1(TP) U19.2(TD0+) UM1.1(MDI[0]+)
MDI0-: TP78.1(TP) U19.3(TD0-) UM1.2(MDI[0]-)
MDI1+: TP76.1(TP) U19.4(TD1+) UM1.4(MDI[1]+)
MDI1-: TP75.1(TP) U19.7(TD1-) UM1.5(MDI[1]-)
MDI2+: TP74.1(TP) U19.5(TD2+) UM1.6(MDI[2]+)
MDI2-: TP73.1(TP) U19.6(TD2-) UM1.7(MDI[2]-)
MDI3+: TP72.1(TP) U19.8(TD3+) UM1.9(MDI[3]+)
MDI3-: TP71.1(TP) U19.9(TD3-) UM1.10(MDI[3]-)
MDIO: RM9.1 RM16.1 UM1.14(MDIO)
MIC1N-MIC: C58.1 C88.1 C89.2 D10.2(CATHODE) MIC1.2(-) R23.2
MIC1P-MIC: C52.1 C83.1 C88.2 D35.2(CATHODE) MIC1.1(+) R20.2
MICIN1N: C58.2 U901.90(MICIN1N)
MICIN1P: C52.2 U901.89(MICIN1P)
MICRO-USB0-DM: D25.1(ANODE) U51.6(HSD1-) USB1.2(D-)
MICRO-USB0-DP: D26.1(ANODE) U51.7(HSD1+) USB1.3(D+)
MIPI-DSI-CKN: J7.9(CLKN) TP56.1(TP) U901.143(MIPI_DSI_CKN)
MIPI-DSI-CKP: J7.8(CLKP) TP57.1(TP) U901.142(MIPI_DSI_CKP)
MIPI-DSI-D0N: J7.3(D0N) TP52.1(TP) U901.137(MIPI_DSI_D0N)
MIPI-DSI-D0P: J7.2(D0P) TP53.1(TP) U901.136(MIPI_DSI_D0P)
MIPI-DSI-D1N: J7.6(D1N) TP54.1(TP) U901.139(MIPI_DSI_D1N)
MIPI-DSI-D1P: J7.5(D1P) TP55.1(TP) U901.138(MIPI_DSI_D1P)
MIPI-DSI-D2N: J7.12(D2N) TP58.1(TP) U901.141(MIPI_DSI_D2N)
MIPI-DSI-D2P: J7.11(D2P) TP59.1(TP) U901.140(MIPI_DSI_D2P)
MIPI-DSI-D3N: J7.15(D3N) TP60.1(TP) U901.145(MIPI_DSI_D3N)
MIPI-DSI-D3P: J7.14(D3P) TP61.1(TP) U901.144(MIPI_DSI_D3P)
NALE-eMMC-RST: U901.77(EMMC_RST) UM2.12
NDQ0-eMMC-D7: U901.86(EMMC_D7) UM2.31
NDQ1-eMMC-D2: U901.84(EMMC_D2) UM2.27
NDQ2-eMMC-D6: U901.83(EMMC_D6) UM2.33
NDQ3-eMMC-D1: U901.81(EMMC_D1) UM2.29
NDQ4-eMMC-D5: U901.82(EMMC_D5) UM2.2
NDQ5-eMMC-D0: U901.85(EMMC_D0) UM2.6
NDQ6-eMMC-D4: U901.79(EMMC_D4) UM2.4
NDQ7-eMMC-D3: U901.80(EMMC_D3) UM2.10
NRB0-eMMC-CMD: U901.75(EMMC_CMD) UM2.25
NRE: RM50.2 UM2.8
NRE-eMMC-CLK: RM50.1 U901.76(EMMC_CLK)
NWE-eMMC-DS: U901.78(EMMC_DS) UM2.15
OVCUR1#: R237.2 R263.1 U32.21(OVCUR1#)
PA-SHDN: R182.2 U901.53(PA_SHDN)
PH4: J56.1 RU13.1 U901.56(PH4) UU3.4(EN)
PH10: J56.2 R549.2 U901.52(PH10)
PHYRST: CM14.1 Q23.3(D) RM21.1 RM45.2 UM1.12(PHYRSTB)
PHYRSTB: Q23.2(S) RM45.1 U901.16(RGMII_RESET)
PS: C291.2 C294.2 J11.2 J11.4 L12.1 U39.6(VIN) U901.35(PS1) U901.36(PS2)
PWKEY: CL67.1 DL52.2(CATHODE) QL13.3(C) U27.3(PWKEY)
PWR-LED: RL6.2 RL56.2 RL57.2 U901.55(LED_PWR)
PWRON: CK15.1 RP62.2 U901.7(PWRON)
REGOUT: CM17.2 LM1.1 RM42.2 UM1.30(REG_OUT)
RF-IN: RG3.1 U8.11(RF_IN)
RGMII-CLKIN-125M: R436.1 R541.1 U901.17(RGMII_CLKIN_125M)
RGMII-CLKIN-125M#: CM13.1 R541.2 RM14.2
RGMII-MDC: R442.1 R546.1 U901.23(RGMII_MDC)
RGMII-MDC#: R546.2 RM8.2
RGMII-MDIO: RM9.2 U901.26(RTGMII_MDIO)
RGMII-RXCK: R434.1 R537.1 U901.14(RGMII_RXCK)
RGMII-RXCK#: CM12.1 R537.2 RM13.2
RGMII-RXCTL: R435.1 R539.1 U901.15(RGMII_RXCTL)
RGMII-RXCTL#: R539.2 RM17.2
RGMII-RXD0: R433.1 R538.1 U901.13(RGMII_RXD0)
RGMII-RXD0#: R538.2 RM15.4(R4)
RGMII-RXD1: R432.1 R535.1 U901.12(RGMII_RXD1)
RGMII-RXD1#: R535.2 RM15.3(R3)
RGMII-RXD2: R431.1 R536.1 U901.11(RGMII_RXD2)
RGMII-RXD2#: R536.2 RM15.2(R2)
RGMII-RXD3: R430.1 R534.1 U901.10(RGMII_RXD3)
RGMII-RXD3#: R534.2 RM15.1(R1)
RGMII-TXCK: R441.1 R545.1 U901.18(RGMII_TXCK)
RGMII-TXCK#: R545.2 RM12.2
RGMII-TXCTL: R522.1 R547.1 U901.25(RGMII)TXCTL)
RGMII-TXCTL#: R547.2 RM54.2
RGMII-TXD0: R440.1 R544.1 U901.22(RGMII_TXD0)
RGMII-TXD0#: R544.2 RM5.1(R1)
RGMII-TXD1: R439.1 R543.1 U901.21(RGMII_TXD1)
RGMII-TXD1#: R543.2 RM5.2(R2)
RGMII-TXD2: R438.1 R542.1 U901.20(RGMII_TXD2)
RGMII-TXD2#: R542.2 RM5.3(R3)
RGMII-TXD3: R437.1 R540.1 U901.19(RGMII_TXD3)
RGMII-TXD3#: R540.2 RM5.4(R4)
RSET: R50.1 UM1.39(RSET)
RXC/PHYAD1: RM13.1 RM38.1 RM39.2 UM1.27(RXC/PHYAD1)
RXCTL/PHYAD2: RM17.1 RM40.1 RM41.2 UM1.26(RXCTL/PHYAD2)
RXD0/RXDLY: RM15.5(R5) RM24.1 RM25.2 UM1.25(RXD0/RXDLY)
RXD1/TXDLY: RM15.6(R6) RM22.1 RM23.2 UM1.24(RXD1/TXDLY)
RXD2/PLLOFF: RM15.7(R7) RM18.1 RM19.2 UM1.23(RXD2/PLLOFF)
RXD3/PHYAD0: RM15.8(R8) RM36.1 RM37.2 UM1.22(RXD3/PHYAD0)
S-TWI1-SCK: J35.3 R77.1 U901.119(S_TWI1_SCK) U902.12(SCX)
S-TWI1-SDA: J35.4 R78.1 U901.118(S_TWI1_SDA) U902.2(SDI)
SDC0-CLK: D11.1(ANODE) J3.5(CLK) U901.100(SDC0_CLK)
SDC0-CMD: D12.1(ANODE) J3.3(CMD) U901.101(SDC0_CMD)
SDC0-D0: D15.1(ANODE) J3.7(DAT0) U901.99(SDC0_D0)
SDC0-D1: D16.1(ANODE) J3.8(DAT1) U901.98(SDC0_D1)
SDC0-D2: D14.1(ANODE) J3.1(DAT2) U901.103(SDC0_D2)
SDC0-D3: D13.1(ANODE) J3.2(DAT3) RC9.1 U901.102(SDC0_D3)
SDC0-DET: R401.2 U901.104(SDC0_DET)
TS: J1.2 U901.29(TS)
TWI1-SCK: J36.3 JL6.6(CTP-SCL) R41.2 R75.1 R531.1 U11.2 U901.5(TWI1_SCK)
TWI1-SDA: J36.4 JL6.5(CTP-SDA) R40.2 R76.1 R532.1 U11.1 U901.6(TWI1_SDA)
TXC: CM11.1 RM12.1 UM1.20(TXC)
TXCTL: RM54.1 UM1.19(TXCTL)
TXD0: RM5.8(R8) UM1.18(TXD0)
TXD1: RM5.7(R7) UM1.17(TXD1)
TXD2: RM5.6(R6) UM1.16(TXD2)
TXD3: RM5.5(R5) UM1.15(TXD3)
UART4_RX: Q2.2(S) R13.1 RG1.1 RG4.1 U901.4(UART4_RX)
UART4_TX: R348.2 RG2.1 RG5.1 U901.3(UART4_TX)
USB1-DM: U51.4(D-) U901.49(USB1_DM)
USB1-DP: U51.3(D+) U901.48(USB1_DP)
USB1_DM: U32.25(DM0) U51.8(HSD2-)
USB1_DP: U32.26(DP0) U51.9(HSD2+)
USB-SEL: R419.1 U51.2(SEL)
USB_RESET: C218.2 R229.1 R238.2 U32.13(\\~{RESE}T)
USBVBUS: C185.2 C186.2 C192.2 C193.2 J9.4(VBUS4) J9.8(VUSB2) RU12.2 U27.11(USB_VBUS) UU3.1(OUT)
USIM_CLK: CL29.1 RL25.1 U27.19(USIM_CLK)
USIM_DATA: CW30.1 RL40.2 U27.17(USIM_DATA)
USIM_RST: CL28.1 RL24.1 U27.18(USIM_RST)
USIM_VDD: CL31.1 CL32.1 JL26.C6(VPP) RL41.1 TP83.1(TP) U27.20(USIM_VDD)
V-BAT: CL46.2 CL48.2 CL80.2 CL81.2 CL82.2 CL86.2 OC5.1 OC6.1 RL45.1 U27.62(VBAT3) U27.63(VBAT4)
VLED+: C293.2 C295.2 D41.2 J7.35(A1) J7.36(A2) TP67.1(TP) U39.5(VOUT)
VLED-: J7.28(K1) J7.29(K2) R315.1 R318.2 TP64.1(TP)
WL-PMU-EN: R527.2 U12.9(WL-REG-ON) U901.154(WL_PMU_EN)
WL-SDIO-CLK: U12.3(CLK) U901.150(WL_SDIO_CLK)
WL-SDIO-CMD: U12.7(CMD) U901.151(WL_SDIO_CMD)
WL-SDIO-D0: U12.2(D0) U901.149(WL_SDIO_D0)
WL-SDIO-D1: U12.4(D1) U901.148(WL_SDIO_D1)
WL-SDIO-D2: U12.6(D2) U901.153(WL_SDIO_D2)
WL-SDIO-D3: U12.8(D3) U901.152(WL_SDIO_D3)
WL-WAKE-AP: U12.11(WL-WAKE-AP) U901.106(WL_WAKE_AP)
X1: C338.1 U32.6(X1) Y3.1
X32KFOUT: U12.10(AP-CK32) U901.147(X32KFOUT)
XI2: C230.2 U32.7(X2) Y3.3
XTAL-IN: C139.2 UM1.36(XTAL_IN) X3.1(XIN)
XTAL-OUT: R51.2 RM56.1 UM1.37(XTAL_OUT/EXT_CLK)
N17770502: CW27.1 RL20.1 RL23.2
N17770537: CW26.1 RL20.2 U27.82(MAIN_ANT)
N17770634: ANT2.3 RL23.1
N17772040: DL51.2(CATHODE) JL26.C7(I/O) RL40.1 TP84.1(TP)
N17772586: JL26.C1(VCC) RL41.2 TP79.1(TP)
N17773525: CL94.1 RL38.1 UL9.4(EN)
N17773548: CL64.2 RL39.2 RL84.2 UL9.3(FB)
N17773558: CL61.1 CL62.1 CL64.1 CL66.1 CL69.1 LP7.2 RL45.2 RL84.1
N17773576: CL88.2 LP7.1 UL9.6(LX)
N17773604: CL88.1 UL9.1(BS)
N17784951: QL13.1(B) RL69.1 RL70.1
N17956748: DL49.2(CATHODE) JL26.C2(RST) RL24.2 TP80.1(TP)
N17956763: DL50.2(CATHODE) JL26.C3(CLK) RL25.2 TP81.1(TP)
N19642444: C275.2 J3.4(VDD) RC1.2
N19809825: J3.9(CD#) R401.1
N19810892: C56.2 R19.1 R20.1
N19810945: C56.1 R23.1 R24.1
N19811956: D39.2(CATHODE) J21.2(B) R422.2
N19811968: D40.2(CATHODE) J21.4(D) R33.2
N19812150: C384.2 R422.1 R423.1
N19812152: C75.2 R33.1 R421.1
N19829872: KK1.4(6) RK2.1 RK3.2
N19829876: KK2.4(6) RK3.1 RK4.2
N19829887: KK3.4(6) RK4.1 RK5.2
N19829903: KK4.4(6) RK5.1 RK6.2
N19829909: KK5.4(6) RK6.1
N19829940: KP1.4 RP62.1
N19829965: KK6.4(6) RK7.1
N19833462: DH12.2 RH16.1
N19840129: QL5.3(C) RL49.1
N19841860: R45.1 R46.2 U2.4(FB)
N19841911: D7.1 R39.2
N19843250: CG2.2 RG3.2 RG6.1
N19843374: RG4.2 U8.20(TXD0)
N19843376: RG5.2 U8.21(RXD0)
N19843437: ANT3.3(CENTER1) CG3.2 RG6.2
N19850791: R239.2 U32.4(PREF)
N19866924: DL6.2(CATHODE) RL1.2
N19866926: QL1.3(C) RL4.2 RL56.1
N19866930: QL3.3(C) RL1.1 RL13.1
N19866943: QL1.1(B) RL6.1 RL85.1
N19866974: QL3.1(B) RL14.1 RL15.1
N19867123: DL7.2(CATHODE) RL4.1
N19875396: R316.2 R318.1 U39.3(FB)
N19875466: C292.2 R316.1 R319.2
N19875497: D41.1 L12.2 U39.1(LX)
N19890305: R43.1 U2.3(EN)
N19896949: DM1.1(ANODE) RM28.1 RM34.2
N19896956: DM1.2(CATHODE) RM33.1 RM35.1
N19897306: CM18.2 CM19.1 LM1.2 RM42.1 RM43.2 RM44.2
N19897342: C140.2 R51.1 X3.3(XOUT)
N19898869: C206.1 U19.1(VCC)
N19898879: RM55.2 U19.13(Y-)
N19898907: RM2.2 U19.12(G-)
N19916216: J12.5 R348.1
N19916242: J12.4 Q2.3(D)
N19923047: R192.2 U902.11(PS)
N19933444: J80.2 R292.2 R419.2 R420.1
N19963769: C189.1 U23.4(PVSS)
N19963781: R177.2 R179.1 U23.10(INTR)
N19963785: C470.2 R177.1
N19963787: R179.2 R181.2 U23.9(OUTR)
N19963809: R183.2 R184.2 U23.8(UVP)
N19963840: R174.1 R178.1 U23.1(-INL)
N19963846: R178.2 R180.1 U23.2(OUTL)
N19963852: C183.1 R174.2
N19963856: R182.1 R185.1 U23.3(EN)
N19963865: C468.2 U23.6(CP)
N19963871: C468.1 U23.5(CN)
N19965778: RU14.1 UU3.3(ISET)
N19978083: J81.1(IN) R548.2
N19983971: R269.1 U24.3(EN)
N19983972: QL5.1(B) RL48.2
N19984458: R549.1 R550.2 USB1.4(ID)
N22541145: DH2.1(ANODE) JH1.19(HOT_PLUG_DET) RH5.2

Not connected (* = marked no-connect by the designer): J7 20(NC1) 21(NC2) 22(NC3) 23(NC4) 25(NC5) 26(NC6) 31(NC7) 34(NC8) 40(NC9); J12 3*; J21 1(E)* 3(C)*; J79 1(E)* 3(C)*; JH1 14(NC)*; KK1 1* 3*; KK2 1* 3*; KK3 1* 3*; KK4 1* 3*; KK5 1* 3*; KK6 1* 3*; KP1 1* 3*; U8 1(GPIO9)* 2(PRTRG)* 3(GPIO13)* 4(GPIO14)* 5(USBDN)* 6(USBDP)* 14(GPIO2)* 15(GPIO6)* 16(GPIO7)* 17(GPIO8)* 18(GPIO4)* 19(GPIO5)*; U11 11; U13 1(PCM_SYNC) 3(PCM_CLK) 5(PCM_DIN) 7(PCM_DOUT); U24 4(FB); U27 4(RESET)* 6(SPI_CLK)* 7(SPI_MISO)* 8(SPI_MOSI)* 9(SPI_CS)* 16(USB_ID)* 21(SD_CMD)* 22(SD_DATA0)* 23(SD_DATA1) 24(SD_DATA2) 25(SD_DATA3) 26(SD_CLK) 27(KBC1) 28(KBC0) 29(KBR0) 30(KBR2) 31(KBC2) 32(KBC3) 33(KBR1) 34(KBR4) 35(KBR3) 36(KBC4) 38(VBAT1) 39(VBAT2) 42(NC)* 44(VDD_EXT) 45(ISINK) 46(ADC2) 47(ADC1) 48(SD1_DET) 50(GPIO43) 51(NETLIGHT) 52(GPIO41) 53(USIM_DET) 54(FLIGHTMODE) 55(SCL) 56(SDA) 59(AUX_ANT) 66(RTS) 67(CTS) 68(RXD) 69(RI) 70(DCD) 71(TXD) 73(PCM_OUT) 74(PCM_IN) 75(PCM_SYNC) 76(PCM_CLK) 79(GNSS_ANT) 83(COEX1)* 84(COEX2)* 85(COOT_CFG0) 86(COEX3) 87(BOOT_CFG1); U32 14(TEST/SCL)* 17(PSELF)* 18(PGANG)* 19(OVCUR2#)* 20(PWREN2#)* 22(PWREN1#)* 23(V5)*; U902 1(SDO)* 5(INT1)* 6(INT2)* 10(CSB)*; UM2 13 16 17 18 19

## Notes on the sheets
sheet 1
- CON
- GPIO
- TWI
- UART
- ADC
- POWER
- 3.3V/1.8V
- 3.3V
- 1.8V
- 1.8V
- 1.8V
sheet 2
- HDMI
- Differential pairs
  Z0= 100 ohm
- Differential pairs
  Z0= 100 ohm
  HTX2P/N
  HTX1P/N
  HTX0P/N
  HTXCP/N
- 默认使用HDMI PHY的SDA/SCL/CEC
sheet 3
- ETHERNET
- Reserved for EMI
- NOTE: IN RMII MODE ,TXCK IS INOUT Pin
- CLOSE TO PIN11 AND PIN40
- RGMII Power
- CLOSE TO PIN29
- Note 1: RM65 is not needed for ONLY 3.3V RGMII application,
               and DVDDRG can be connected directly to DVDD33.
  Note 2: DVDDRG must be short (or RM6 be mounted) to
               DVDD33 if the external RGMII 3.3V is selected.
  Note 3: RM6 must be removed if the internal or external
               2.5V/1.8V/1.5V RGMII is selected.
  Note 4: CAPs must be closed to pin28 for EMI consideration.
- Green LED for 100M Yellow LED FOR 1000M
- Close to PHY. Reserved for EMI.
  (optional)
- RESERVED
- PHY RESET/INTB
- Enable/Disable PLL @ ALDPS
- Pull-up to disable PLL @ ALDPS mode.
- RGMII TXC/RXC Delay Config.
- Pull-up for additional 2ns delay to TXC/RXC for data latching.
- LEDs Configuration
- Reserved for EMI
- RGMII Voltage Config.
- RGMII Power Source
- CFG_EXT
- CFG_LDO[1:0]
- External 2.5V
- External 3.3V (default)
- 1'b1
- 1'b1
- 2'b00
- 2'b01
- External 1.8V
- 1'b1
- 2'b10
- External 1.5V
- 1'b1
- 2'b11
- Internal 2.5V
- 1'b0
- 2'b01
- Internal 1.8V
- 1'b0
- 2'b10
- PHY Address Config.
- Internal 1.5V
- 1'b0
- 2'b11
- PHY Address
- PHYAD[2:0]
- 0
- 3'b000
- 1 (default)
- 3'b001
sheet 4
- SIM7600
- There should be ground clearance
  around antenna.
- 3V8@2A
- R1
- R2
- Vout=
  0.6*(1+R1/R2)
sheet 5
- 1.8V
- 3.3V
- 1.8V
- 3.3V/1.8V
- 1.8V
- 3.3V
sheet 6
- WIFI
- APXXX
sheet 7
- SPEAKER
- AUDIO
- MIC(Electret)
- C1
- C3
- R1
- D1
- C2
- R2
- Close to MIC
- Close to AP
- COMPONENT
- Diferential
- Single-ended
- R1 R2 C1 C3 D1
- USE
- NC
- C2
- 33pF
- 0R
- I2S CONN
- FOR EXTERNAL AC108
- LINE IN
sheet 8
- 3.3V
- 1.8V
- DC-5V
- 1.8V
- 减小AVCC与其他电源公共路径
- 3.3V/1.8V
- RTC
- Vout = 0.8*(1+R1/R2)
  Vout=1.7V
- 3.3V
- R1
- 1.8V
- R2
- SINK FROM VINT WHEN PMIC POWER IS PRESENT
- BAT
- IMAX=2A
- place several GND TEST POINTs around the board
- For 3g
sheet 9
- Flash
- eMMC NAND和TSOP NAND LAYOUT together
sheet 10
- DVP
- Force booting from USB0 by pull FEL LOW.
  internally pull high
- 1.8V
- 0.115V
- 0.235V
- 0.36V
- 0.476V
- 0.592V
- KEY
sheet 11
- CARD
- NOTE:
  VCC-CARD: fixed to 3.3V
  SCD0-DET SDC0-CMD: use nternal pull-up
- Option
  used D3 for card detect.
  default not be used.
- USB HUB
- USB
- 500mA
- MAX=1.5A
- Ilim (A)=6800/Rset (ohm)
- Note:
- USB-SEL
- MICRO-USB
- 4G-USB
- L
- ON
- OFF
- H
- OFF
- ON
- eMMC NAND和TSOP NAND LAYOUT together
sheet 12
- LCD/CTP
- CTP CN
- NOTE:CTP CONNECTOR
- MIPI-DSI
- Backlight
- R=200mV/I(led)
sheet 13
- G-SENSOR
- LED
- GPS
- 50 Ohm RF trace
- 50 ohm
- HDM1216D
